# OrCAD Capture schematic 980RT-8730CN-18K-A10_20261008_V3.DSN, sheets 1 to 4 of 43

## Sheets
1 A0000_Config_C3680RF
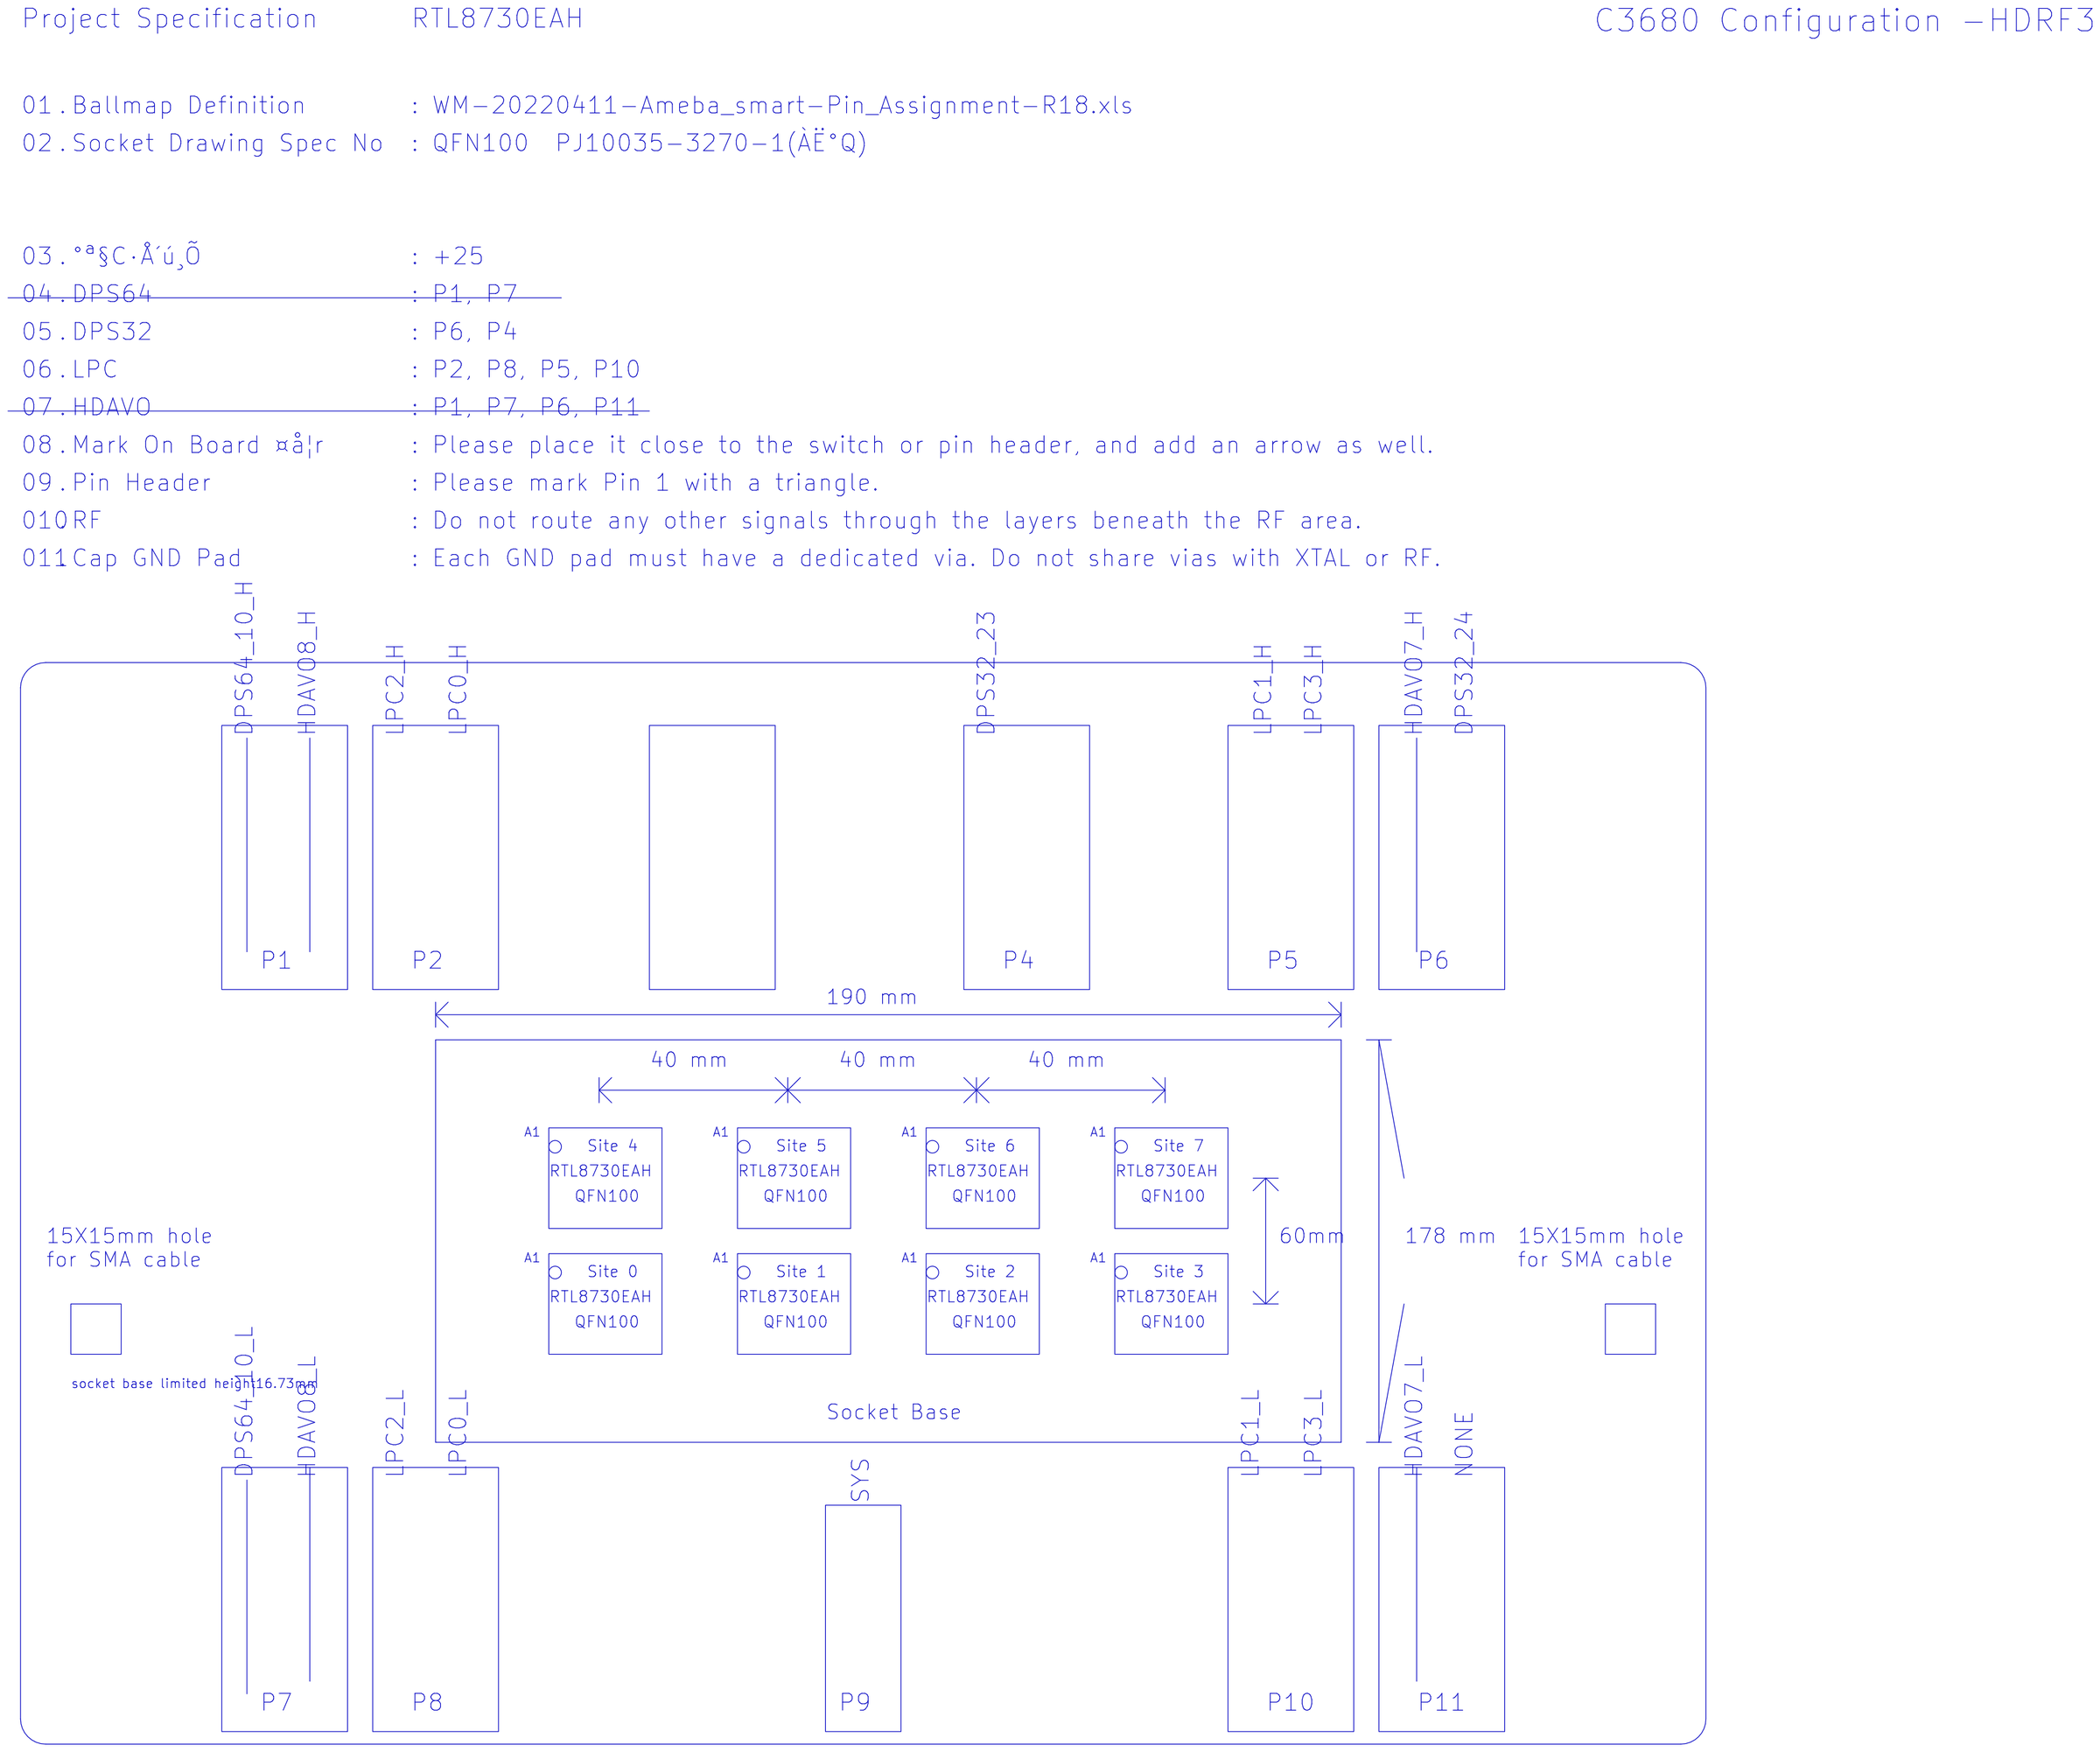
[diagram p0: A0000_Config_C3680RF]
2 P0001_S0_DUT1: size Custom
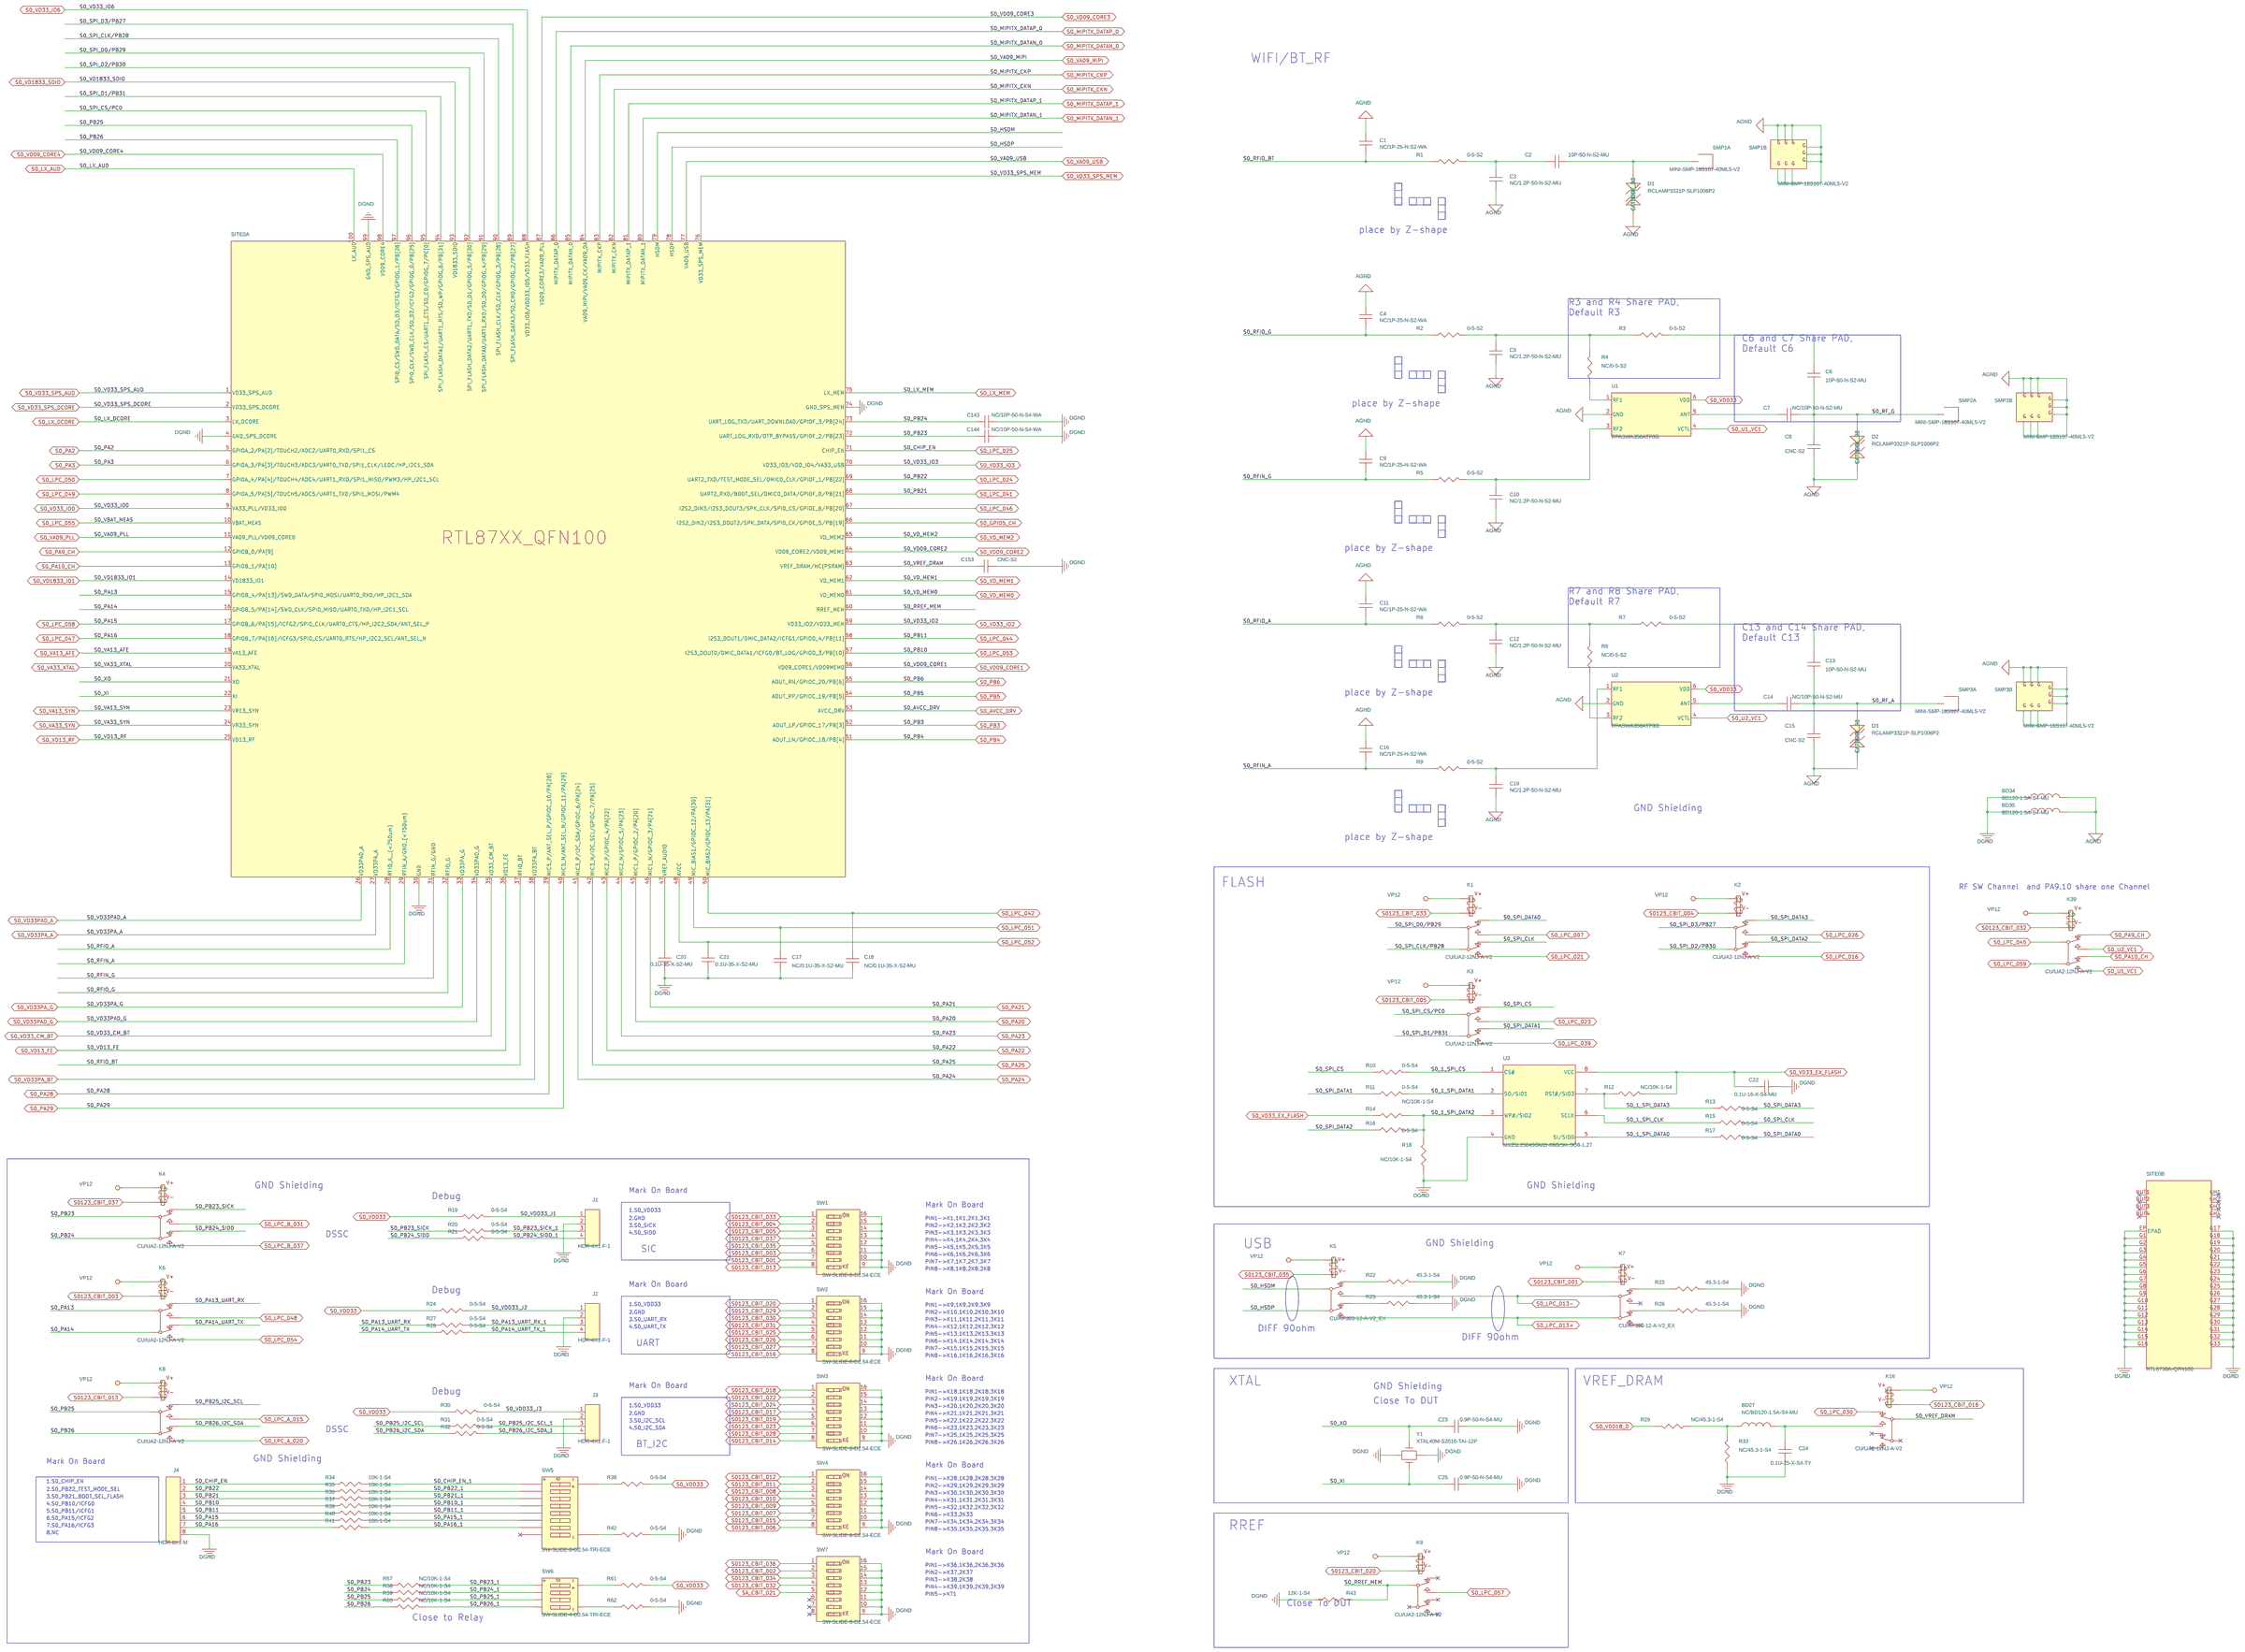
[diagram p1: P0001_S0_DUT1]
3 P0002_S0_Function-test: size A3
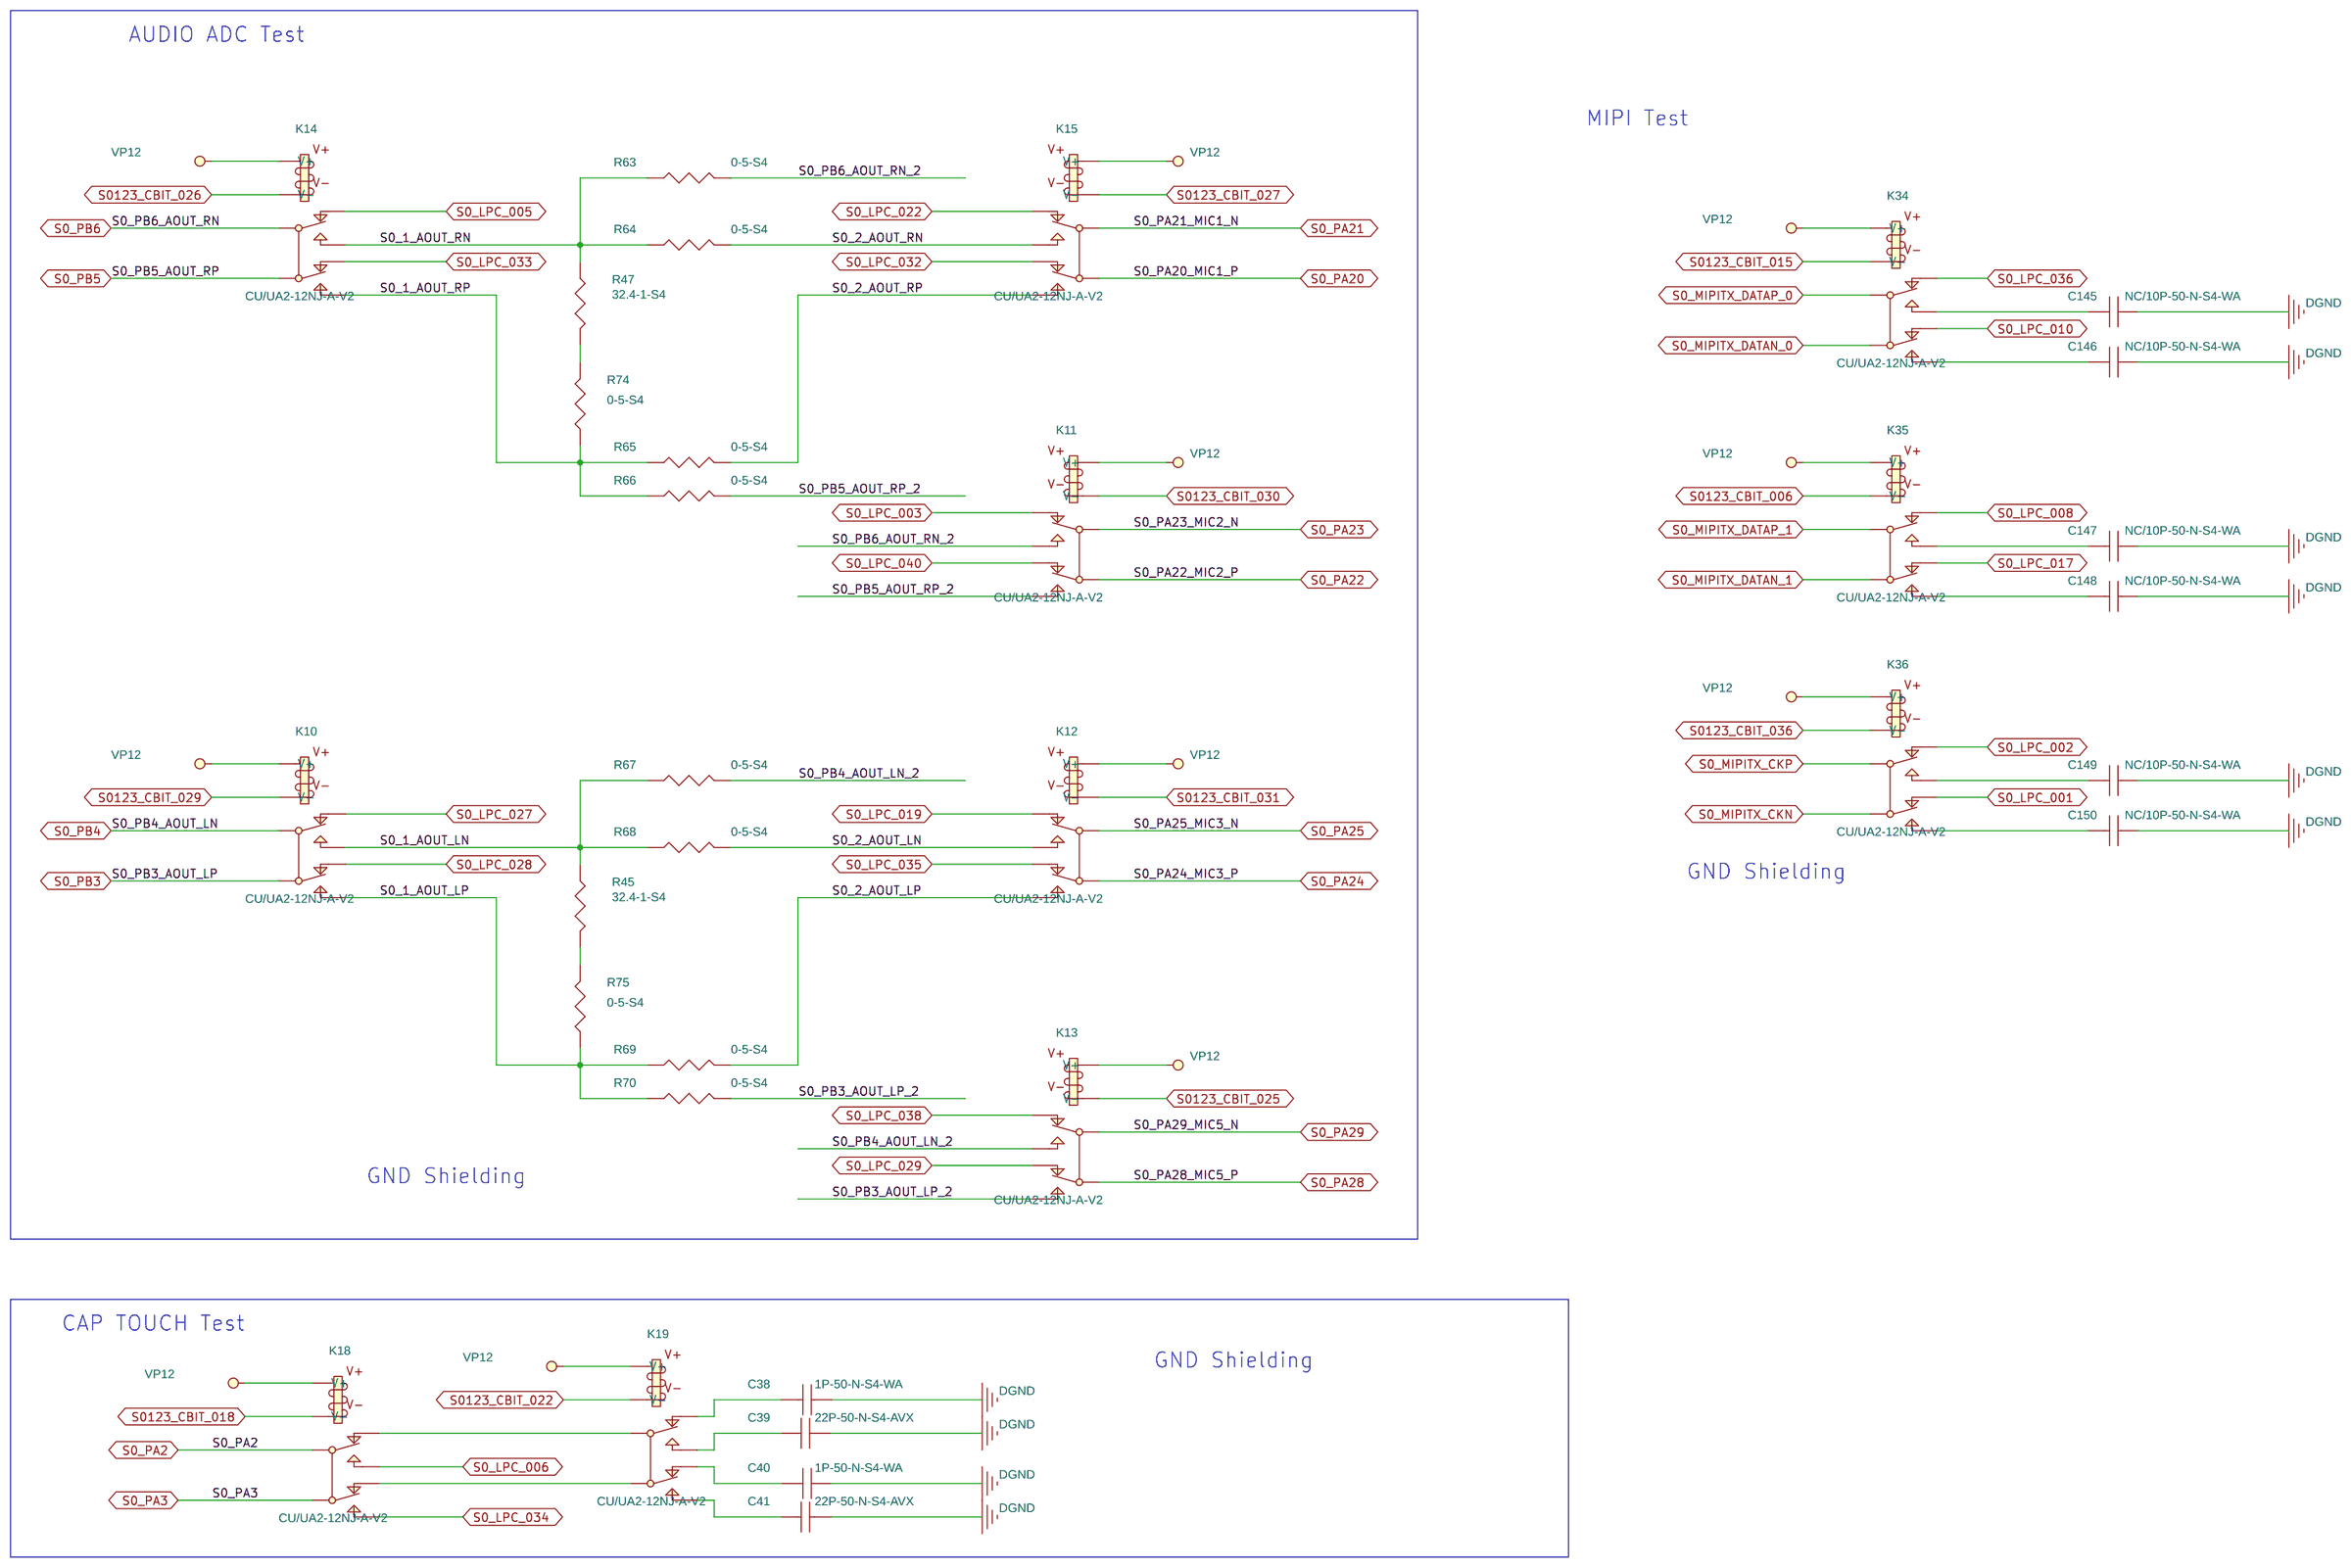
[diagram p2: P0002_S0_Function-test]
4 P0003_S0_Power: size A1
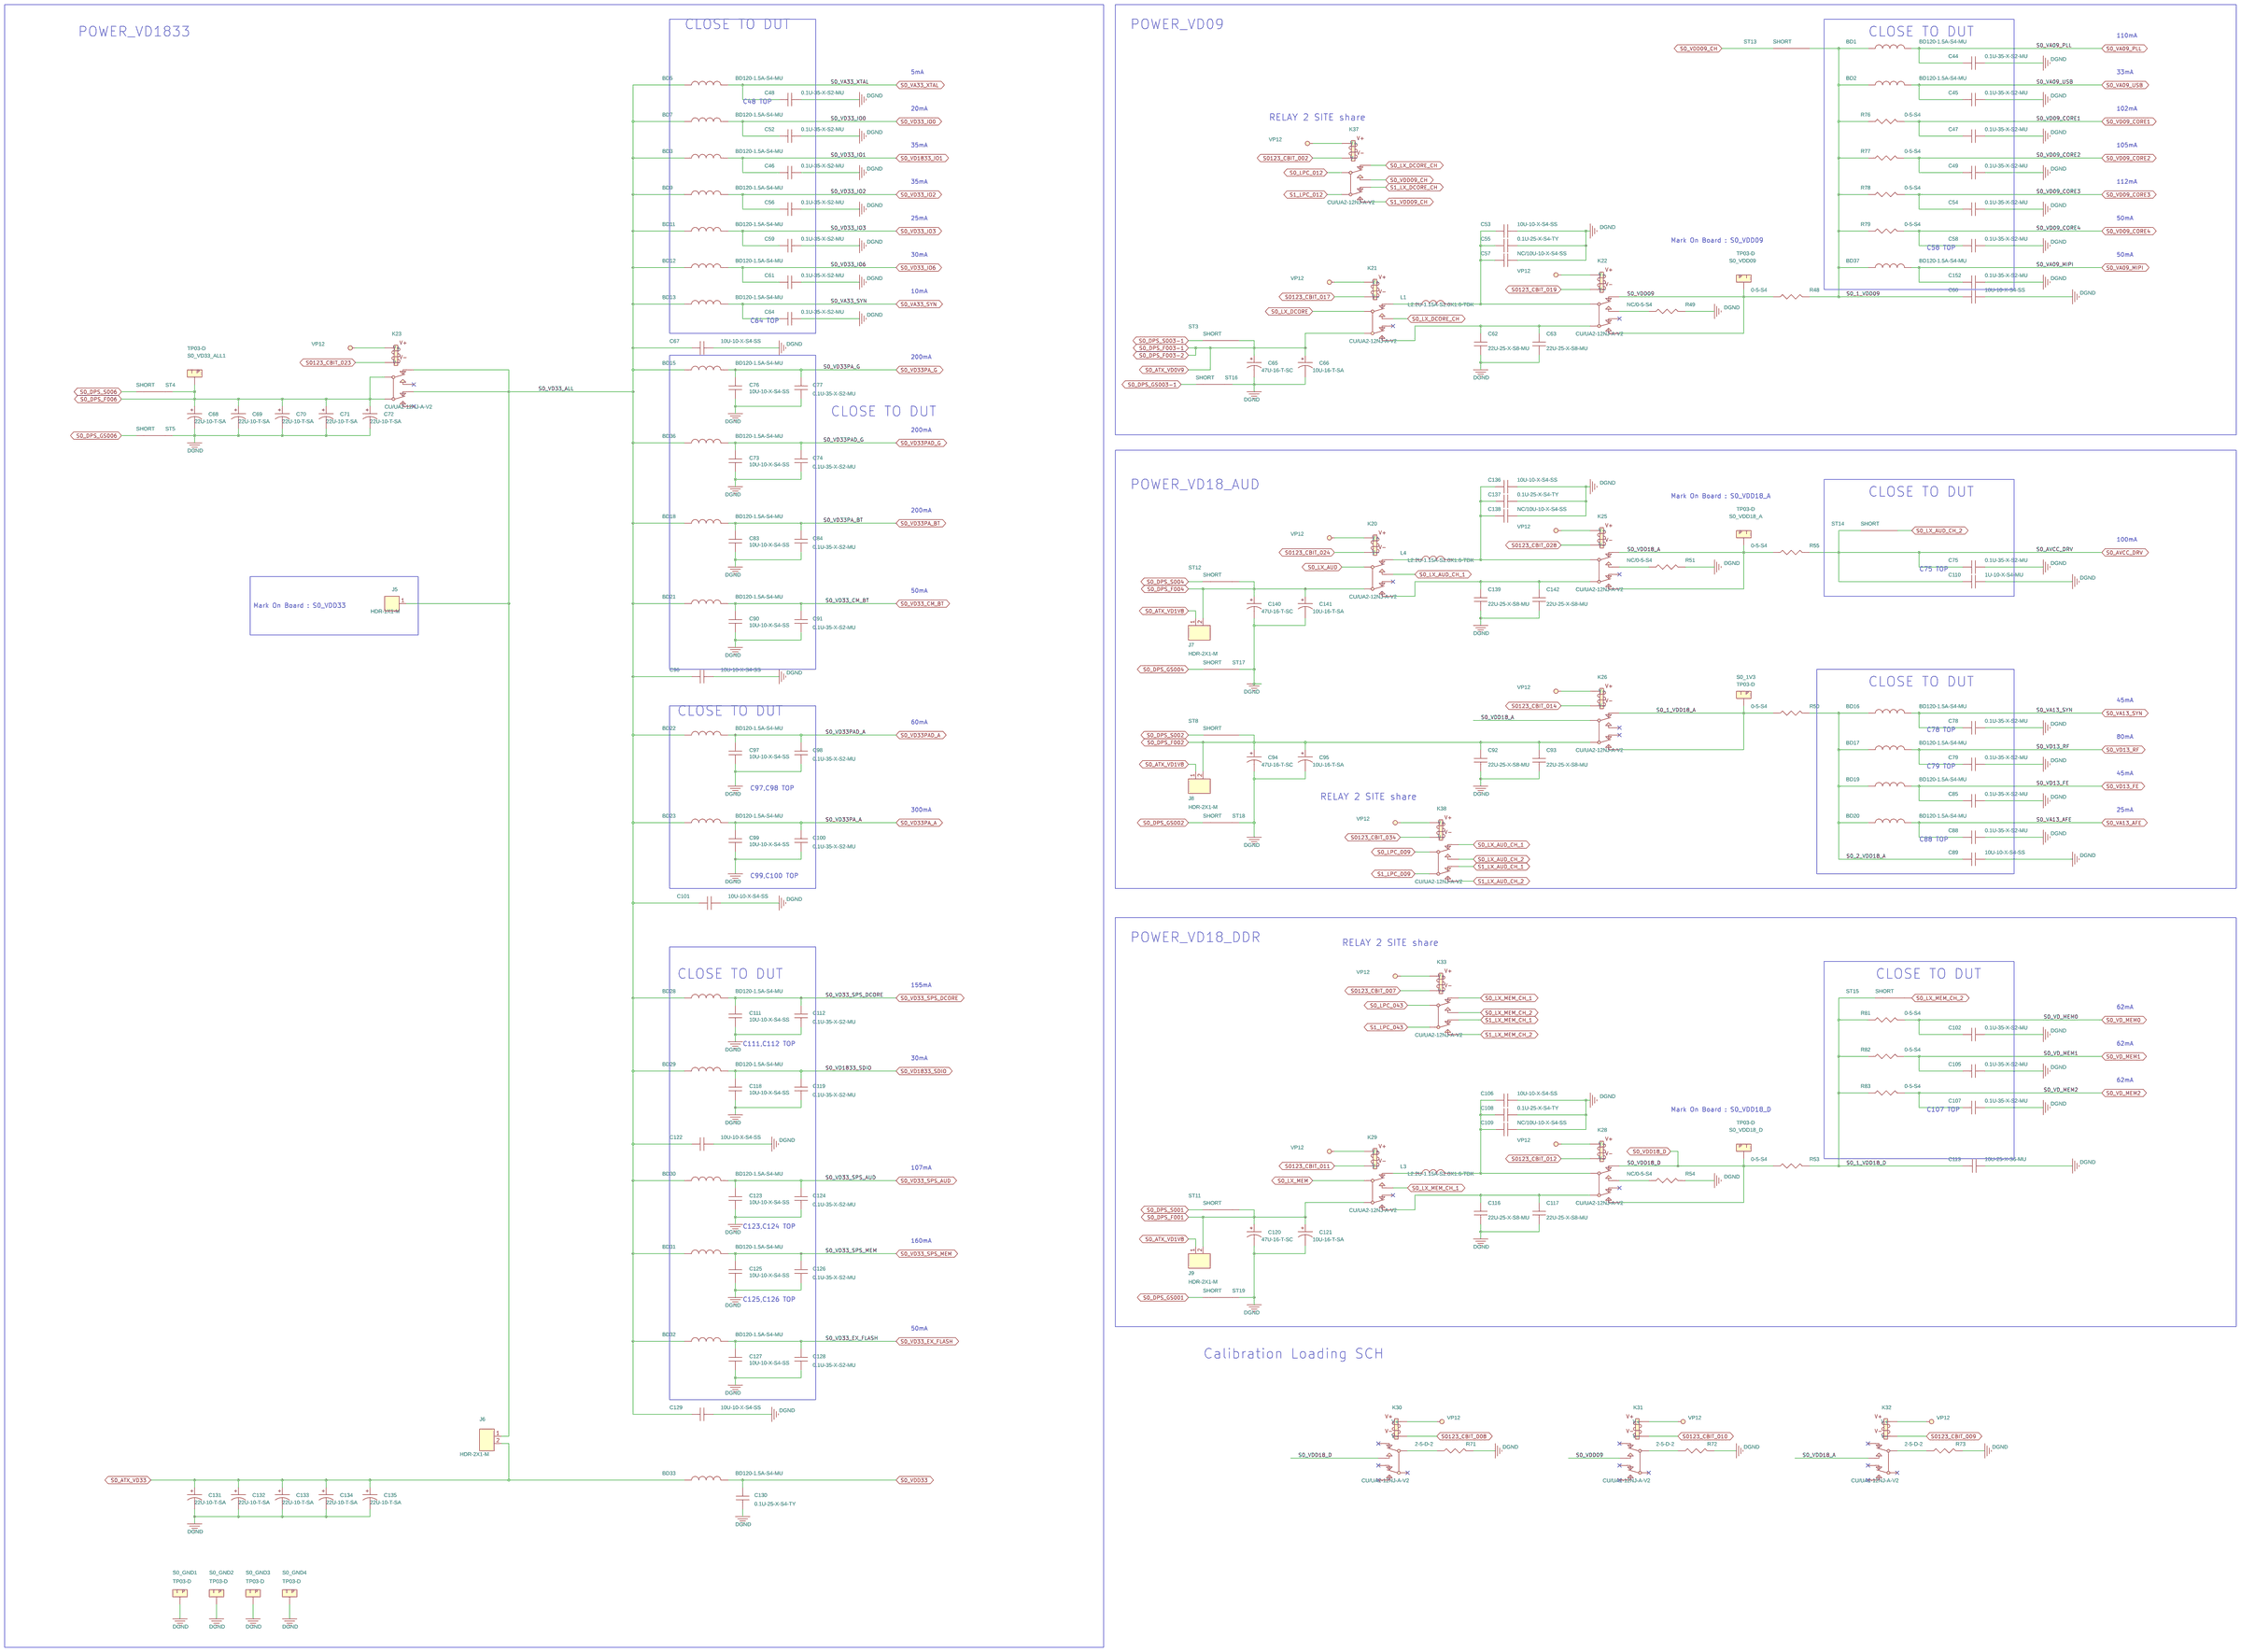
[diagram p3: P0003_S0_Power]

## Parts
sheet P0001_S0_DUT1
BD27  NC/BD120-1.5A-S4-MU  [FB0402]
BD34  BD120-1.5A-S4-MU  [FB0402]
BD35  BD120-1.5A-S4-MU  [FB0402]
C1  NC/1P-25-N-S2-WA  [C0201]
C2  10P-50-N-S2-MU  [C0201]
C3  NC/1.2P-50-N-S2-MU  [C0201]
C4  NC/1P-25-N-S2-WA  [C0201]
C5  NC/1.2P-50-N-S2-MU  [C0201]
C6  10P-50-N-S2-MU  [C0201]
C7  NC/10P-50-N-S2-MU  [C0201]
C8  CNC-S2  [C0201]
C9  NC/1P-25-N-S2-WA  [C0201]
C10  NC/1.2P-50-N-S2-MU  [C0201]
C11  NC/1P-25-N-S2-WA  [C0201]
C12  NC/1.2P-50-N-S2-MU  [C0201]
C13  10P-50-N-S2-MU  [C0201]
C14  NC/10P-50-N-S2-MU  [C0201]
C15  CNC-S2  [C0201]
C16  NC/1P-25-N-S2-WA  [C0201]
C17  NC/0.1U-35-X-S2-MU  [C0201]
C18  NC/0.1U-35-X-S2-MU  [C0201]
C19  NC/1.2P-50-N-S2-MU  [C0201]
C20  0.1U-35-X-S2-MU  [C0201]
C21  0.1U-35-X-S2-MU  [C0201]
C22  0.1U-16-X-S4-MU  [C0402]
C23  0.9P-50-N-S4-MU  [C0402]
C24  0.1U-25-X-S4-TY  [C0402]
C25  0.9P-50-N-S4-MU  [C0402]
C143  NC/10P-50-N-S4-WA  [C0402]
C144  NC/10P-50-N-S4-WA  [C0402]
C153  CNC-S2  [C0201]
D1  RCLAMP3321P-SLP1006P2  [DIODE_1X0P6MM]
D2  RCLAMP3321P-SLP1006P2  [DIODE_1X0P6MM]
D3  RCLAMP3321P-SLP1006P2  [DIODE_1X0P6MM]
J1  HDR-4X1-F-1  [CONN_4X1_2P54MM_FL10P5MM]
J2  HDR-4X1-F-1  [CONN_4X1_2P54MM_FL10P5MM]
J3  HDR-4X1-F-1  [CONN_4X1_2P54MM_FL10P5MM]
J4  HDR-8X1-M  [JP_8P_100]
K1  CU/UA2-12NJ-A-V2  [RL_NECUA2_12V_V2]
K2  CU/UA2-12NJ-A-V2  [RL_NECUA2_12V_V2]
K3  CU/UA2-12NJ-A-V2  [RL_NECUA2_12V_V2]
K4  CU/UA2-12NJ-A-V2  [RL_NECUA2_12V_V2]
K5  CU/RF303-12-A-V2_EX  [RL_RF303_12V_V2]
K6  CU/UA2-12NJ-A-V2  [RL_NECUA2_12V_V2]
K7  CU/RF303-12-A-V2_EX  [RL_RF303_12V_V2]
K8  CU/UA2-12NJ-A-V2  [RL_NECUA2_12V_V2]
K9  CU/UA2-12NJ-A-V2  [RL_NECUA2_12V_V2]
K16  CU/UA2-12NJ-A-V2  [RL_NECUA2_12V_V2]
K39  CU/UA2-12NJ-A-V2  [RL_NECUA2_12V_V2]
R1  0-5-S2  [R0201]
R2  0-5-S2  [R0201]
R3  0-5-S2  [R0201]
R4  NC/0-5-S2  [R0201]
R5  0-5-S2  [R0201]
R6  0-5-S2  [R0201]
R7  0-5-S2  [R0201]
R8  NC/0-5-S2  [R0201]
R9  0-5-S2  [R0201]
R10  0-5-S4  [R0402]
R11  0-5-S4  [R0402]
R12  NC/10K-1-S4  [R0402]
R13  0-5-S4  [R0402]
R14  NC/10K-1-S4  [R0402]
R15  0-5-S4  [R0402]
R16  0-5-S4  [R0402]
R17  0-5-S4  [R0402]
R18  NC/10K-1-S4  [R0402]
R19  0-5-S4  [R0402]
R20  0-5-S4  [R0402]
R21  0-5-S4  [R0402]
R22  45.3-1-S4  [R0402]
R23  45.3-1-S4  [R0402]
R24  0-5-S4  [R0402]
R25  45.3-1-S4  [R0402]
R26  45.3-1-S4  [R0402]
R27  0-5-S4  [R0402]
R28  0-5-S4  [R0402]
R29  NC/45.3-1-S4  [R0402]
R30  0-5-S4  [R0402]
R31  0-5-S4  [R0402]
R32  0-5-S4  [R0402]
R33  NC/45.3-1-S4  [R0402]
R34  10K-1-S4  [R0402]
R35  10K-1-S4  [R0402]
R36  10K-1-S4  [R0402]
R37  10K-1-S4  [R0402]
R38  0-5-S4  [R0402]
R39  10K-1-S4  [R0402]
R40  10K-1-S4  [R0402]
R41  10K-1-S4  [R0402]
R42  0-5-S4  [R0402]
R43  12K-1-S4  [R0402]
R57  NC/10K-1-S4  [R0402]
R58  NC/10K-1-S4  [R0402]
R59  NC/10K-1-S4  [R0402]
R60  NC/10K-1-S4  [R0402]
R61  0-5-S4  [R0402]
R62  0-5-S4  [R0402]
SITE0  RTL8730A-QFN100  [SK_QFN100P_0P35MM_MJC_L8730A]  (sections A,B)
SMP1  MINI-SMP-18S107-40ML5-V2  [CONN_SMP_18S107]  (sections A,B)
SMP2  MINI-SMP-18S107-40ML5-V2  [CONN_SMP_18S107]  (sections A,B)
SMP3  MINI-SMP-18S107-40ML5-V2  [CONN_SMP_18S107]  (sections A,B)
SW1  SW-SLIDE-8-D2.54-ECE  [SW_DIPX8_16P_H5MM]
SW2  SW-SLIDE-8-D2.54-ECE  [SW_DIPX8_16P_H5MM]
SW3  SW-SLIDE-8-D2.54-ECE  [SW_DIPX8_16P_H5MM]
SW4  SW-SLIDE-8-D2.54-ECE  [SW_DIPX8_16P_H5MM]
SW5  SW-SLIDE-8-D2.54-TRI-ECE  [SW_DIPX8P_2P54_MM_V2]
SW6  SW-SLIDE-4-D2.54-TRI-ECE  [SW_DIPX4P_2P54MM_ETD]
SW7  SW-SLIDE-8-D2.54-ECE  [SW_DIPX8_16P_H5MM]
U1  RFASWA358ATF0G  [RF_SW_GW2159_6P]
U2  RFASWA358ATF0G  [RF_SW_GW2159_6P]
U3  MX25L25645GM2I-08G/SK-SO8-1.27  [SK_SO8_1P27MM_LOTES]
Y1  XTAL40M-S2016-TAI-12P  [XTAL_2X1P6MM_4P_0P8MM]
sheet P0002_S0_Function-test
C38  1P-50-N-S4-WA  [C0402]
C39  22P-50-N-S4-AVX  [C0402]
C40  1P-50-N-S4-WA  [C0402]
C41  22P-50-N-S4-AVX  [C0402]
C145  NC/10P-50-N-S4-WA  [C0402]
C146  NC/10P-50-N-S4-WA  [C0402]
C147  NC/10P-50-N-S4-WA  [C0402]
C148  NC/10P-50-N-S4-WA  [C0402]
C149  NC/10P-50-N-S4-WA  [C0402]
C150  NC/10P-50-N-S4-WA  [C0402]
K10  CU/UA2-12NJ-A-V2  [RL_NECUA2_12V_V2]
K11  CU/UA2-12NJ-A-V2  [RL_NECUA2_12V_V2]
K12  CU/UA2-12NJ-A-V2  [RL_NECUA2_12V_V2]
K13  CU/UA2-12NJ-A-V2  [RL_NECUA2_12V_V2]
K14  CU/UA2-12NJ-A-V2  [RL_NECUA2_12V_V2]
K15  CU/UA2-12NJ-A-V2  [RL_NECUA2_12V_V2]
K18  CU/UA2-12NJ-A-V2  [RL_NECUA2_12V_V2]
K19  CU/UA2-12NJ-A-V2  [RL_NECUA2_12V_V2]
K34  CU/UA2-12NJ-A-V2  [RL_NECUA2_12V_V2]
K35  CU/UA2-12NJ-A-V2  [RL_NECUA2_12V_V2]
K36  CU/UA2-12NJ-A-V2  [RL_NECUA2_12V_V2]
R45  32.4-1-S4  [R0402]
R47  32.4-1-S4  [R0402]
R63  0-5-S4  [R0402]
R64  0-5-S4  [R0402]
R65  0-5-S4  [R0402]
R66  0-5-S4  [R0402]
R67  0-5-S4  [R0402]
R68  0-5-S4  [R0402]
R69  0-5-S4  [R0402]
R70  0-5-S4  [R0402]
R74  0-5-S4  [R0402]
R75  0-5-S4  [R0402]
sheet P0003_S0_Power
BD1  BD120-1.5A-S4-MU  [FB0402]
BD2  BD120-1.5A-S4-MU  [FB0402]
BD3  BD120-1.5A-S4-MU  [FB0402]
BD5  BD120-1.5A-S4-MU  [FB0402]
BD7  BD120-1.5A-S4-MU  [FB0402]
BD9  BD120-1.5A-S4-MU  [FB0402]
BD11  BD120-1.5A-S4-MU  [FB0402]
BD12  BD120-1.5A-S4-MU  [FB0402]
BD13  BD120-1.5A-S4-MU  [FB0402]
BD15  BD120-1.5A-S4-MU  [FB0402]
BD16  BD120-1.5A-S4-MU  [FB0402]
BD17  BD120-1.5A-S4-MU  [FB0402]
BD18  BD120-1.5A-S4-MU  [FB0402]
BD19  BD120-1.5A-S4-MU  [FB0402]
BD20  BD120-1.5A-S4-MU  [FB0402]
BD21  BD120-1.5A-S4-MU  [FB0402]
BD22  BD120-1.5A-S4-MU  [FB0402]
BD23  BD120-1.5A-S4-MU  [FB0402]
BD28  BD120-1.5A-S4-MU  [FB0402]
BD29  BD120-1.5A-S4-MU  [FB0402]
BD30  BD120-1.5A-S4-MU  [FB0402]
BD31  BD120-1.5A-S4-MU  [FB0402]
BD32  BD120-1.5A-S4-MU  [FB0402]
BD33  BD120-1.5A-S4-MU  [FB0402]
BD36  BD120-1.5A-S4-MU  [FB0402]
BD37  BD120-1.5A-S4-MU  [FB0402]
C44  0.1U-35-X-S2-MU  [C0201]
C45  0.1U-35-X-S2-MU  [C0201]
C46  0.1U-35-X-S2-MU  [C0201]
C47  0.1U-35-X-S2-MU  [C0201]
C48  0.1U-35-X-S2-MU  [C0201]
C49  0.1U-35-X-S2-MU  [C0201]
C52  0.1U-35-X-S2-MU  [C0201]
C53  10U-10-X-S4-SS  [C0402]
C54  0.1U-35-X-S2-MU  [C0201]
C55  0.1U-25-X-S4-TY  [C0402]
C56  0.1U-35-X-S2-MU  [C0201]
C57  NC/10U-10-X-S4-SS  [C0402]
C58  0.1U-35-X-S2-MU  [C0201]
C59  0.1U-35-X-S2-MU  [C0201]
C60  10U-10-X-S4-SS  [C0402]
C61  0.1U-35-X-S2-MU  [C0201]
C62  22U-25-X-S8-MU  [C0805]
C63  22U-25-X-S8-MU  [C0805]
C64  0.1U-35-X-S2-MU  [C0201]
C65  47U-16-T-SC  [CODE_C]
C66  10U-16-T-SA  [CODE_A]
C67  10U-10-X-S4-SS  [C0402]
C68  22U-10-T-SA  [CODE_A]
C69  22U-10-T-SA  [CODE_A]
C70  22U-10-T-SA  [CODE_A]
C71  22U-10-T-SA  [CODE_A]
C72  22U-10-T-SA  [CODE_A]
C73  10U-10-X-S4-SS  [C0402]
C74  0.1U-35-X-S2-MU  [C0201]
C75  0.1U-35-X-S2-MU  [C0201]
C76  10U-10-X-S4-SS  [C0402]
C77  0.1U-35-X-S2-MU  [C0201]
C78  0.1U-35-X-S2-MU  [C0201]
C79  0.1U-35-X-S2-MU  [C0201]
C83  10U-10-X-S4-SS  [C0402]
C84  0.1U-35-X-S2-MU  [C0201]
C85  0.1U-35-X-S2-MU  [C0201]
C88  0.1U-35-X-S2-MU  [C0201]
C89  10U-10-X-S4-SS  [C0402]
C90  10U-10-X-S4-SS  [C0402]
C91  0.1U-35-X-S2-MU  [C0201]
C92  22U-25-X-S8-MU  [C0805]
C93  22U-25-X-S8-MU  [C0805]
C94  47U-16-T-SC  [CODE_C]
C95  10U-16-T-SA  [CODE_A]
C96  10U-10-X-S4-SS  [C0402]
C97  10U-10-X-S4-SS  [C0402]
C98  0.1U-35-X-S2-MU  [C0201]
C99  10U-10-X-S4-SS  [C0402]
C100  0.1U-35-X-S2-MU  [C0201]
C101  10U-10-X-S4-SS  [C0402]
C102  0.1U-35-X-S2-MU  [C0201]
C105  0.1U-35-X-S2-MU  [C0201]
C106  10U-10-X-S4-SS  [C0402]
C107  0.1U-35-X-S2-MU  [C0201]
C108  0.1U-25-X-S4-TY  [C0402]
C109  NC/10U-10-X-S4-SS  [C0402]
C110  1U-10-X-S4-MU  [C0402]
C111  10U-10-X-S4-SS  [C0402]
C112  0.1U-35-X-S2-MU  [C0201]
C113  10U-25-X-S6-MU  [C0603]
C116  22U-25-X-S8-MU  [C0805]
C117  22U-25-X-S8-MU  [C0805]
C118  10U-10-X-S4-SS  [C0402]
C119  0.1U-35-X-S2-MU  [C0201]
C120  47U-16-T-SC  [CODE_C]
C121  10U-16-T-SA  [CODE_A]
C122  10U-10-X-S4-SS  [C0402]
C123  10U-10-X-S4-SS  [C0402]
C124  0.1U-35-X-S2-MU  [C0201]
C125  10U-10-X-S4-SS  [C0402]
C126  0.1U-35-X-S2-MU  [C0201]
C127  10U-10-X-S4-SS  [C0402]
C128  0.1U-35-X-S2-MU  [C0201]
C129  10U-10-X-S4-SS  [C0402]
C130  0.1U-25-X-S4-TY  [C0402]
C131  22U-10-T-SA  [CODE_A]
C132  22U-10-T-SA  [CODE_A]
C133  22U-10-T-SA  [CODE_A]
C134  22U-10-T-SA  [CODE_A]
C135  22U-10-T-SA  [CODE_A]
C136  10U-10-X-S4-SS  [C0402]
C137  0.1U-25-X-S4-TY  [C0402]
C138  NC/10U-10-X-S4-SS  [C0402]
C139  22U-25-X-S8-MU  [C0805]
C140  47U-16-T-SC  [CODE_C]
C141  10U-16-T-SA  [CODE_A]
C142  22U-25-X-S8-MU  [C0805]
C152  0.1U-35-X-S2-MU  [C0201]
J5  HDR-1X1-M  [JP_1P_RD070_040]
J6  HDR-2X1-M  [JP_2P_100]
J7  HDR-2X1-M  [JP_2P_100]
J8  HDR-2X1-M  [JP_2P_100]
J9  HDR-2X1-M  [JP_2P_100]
K20  CU/UA2-12NJ-A-V2  [RL_NECUA2_12V_V2]
K21  CU/UA2-12NJ-A-V2  [RL_NECUA2_12V_V2]
K22  CU/UA2-12NJ-A-V2  [RL_NECUA2_12V_V2]
K23  CU/UA2-12NJ-A-V2  [RL_NECUA2_12V_V2]
K25  CU/UA2-12NJ-A-V2  [RL_NECUA2_12V_V2]
K26  CU/UA2-12NJ-A-V2  [RL_NECUA2_12V_V2]
K28  CU/UA2-12NJ-A-V2  [RL_NECUA2_12V_V2]
K29  CU/UA2-12NJ-A-V2  [RL_NECUA2_12V_V2]
K30  CU/UA2-12NJ-A-V2  [RL_NECUA2_12V_V2]
K31  CU/UA2-12NJ-A-V2  [RL_NECUA2_12V_V2]
K32  CU/UA2-12NJ-A-V2  [RL_NECUA2_12V_V2]
K33  CU/UA2-12NJ-A-V2  [RL_NECUA2_12V_V2]
K37  CU/UA2-12NJ-A-V2  [RL_NECUA2_12V_V2]
K38  CU/UA2-12NJ-A-V2  [RL_NECUA2_12V_V2]
L1  L2.2U-1.15A-S2.0X1.6-TDK  [IND_VL252012E]
L3  L2.2U-1.15A-S2.0X1.6-TDK  [IND_VL252012E]
L4  L2.2U-1.15A-S2.0X1.6-TDK  [IND_VL252012E]
R48  0-5-S4  [R0402]
R49  NC/0-5-S4  [R0402]
R50  0-5-S4  [R0402]
R51  NC/0-5-S4  [R0402]
R53  0-5-S4  [R0402]
R54  NC/0-5-S4  [R0402]
R55  0-5-S4  [R0402]
R71  2-5-D-2  [RC02W_27MM]
R72  2-5-D-2  [RC02W_27MM]
R73  2-5-D-2  [RC02W_27MM]
R76  0-5-S4  [R0402]
R77  0-5-S4  [R0402]
R78  0-5-S4  [R0402]
R79  0-5-S4  [R0402]
R81  0-5-S4  [R0402]
R82  0-5-S4  [R0402]
R83  0-5-S4  [R0402]
S0_1V3  TP03-D  [TP_060_040]
S0_GND1  TP03-D  [TP_060_040]
S0_GND2  TP03-D  [TP_060_040]
S0_GND3  TP03-D  [TP_060_040]
S0_GND4  TP03-D  [TP_060_040]
S0_VD33_ALL1  TP03-D  [TP_060_040]
S0_VDD09  TP03-D  [TP_060_040]
S0_VDD18_A  TP03-D  [TP_060_040]
S0_VDD18_D  TP03-D  [TP_060_040]
ST3  SHORT  [DEFAULT_SHORT_SMALL]
ST4  SHORT  [DEFAULT_SHORT_SMALL]
ST5  SHORT  [DEFAULT_SHORT_SMALL]
ST8  SHORT  [DEFAULT_SHORT_SMALL]
ST11  SHORT  [DEFAULT_SHORT_SMALL]
ST12  SHORT  [DEFAULT_SHORT_SMALL]
ST13  SHORT  [DEFAULT_SHORT_SMALL]
ST14  SHORT  [DEFAULT_SHORT_SMALL]
ST15  SHORT  [DEFAULT_SHORT_SMALL]
ST16  SHORT  [DEFAULT_SHORT_SMALL]
ST17  SHORT  [DEFAULT_SHORT_SMALL]
ST18  SHORT  [DEFAULT_SHORT_SMALL]
ST19  SHORT  [DEFAULT_SHORT_SMALL]

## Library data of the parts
BD1-BD3 BD5 BD7 BD9 BD11-BD13 BD15-BD23 BD27-BD35 = BD120-1.5A-S4-MU
C1 C4 C9 C11 C16 = 1P-25-N-S2-WA
C2 C6 C7 C13 C14 = 10P-50-N-S2-MU
C3 C5 C10 C12 C19 = 1.2P-50-N-S2-MU
C8 C15 = CNC-S4
C17 C18 = 0.1U-35-X-S2-MU: KAIROSNAME: C46
C20 C21 = 0.1U-35-X-S2-MU: KAIROSNAME: C98
C22 = 0.1U-16-X-S4
C23 C25 C38 C40 = 10P-50-N-S4-MU-1
C24 C55 C108 C130 C137 = 0.1U-25-X-S4-TY
C143-C150 = 10P-50-N-S4-WA
C153 = 0.1U-35-X-S2-MU: KAIROSNAME: C48
D1-D3 = RCLAMP3321P-SLP1006P2
J1-J3 = HDR-4X1-F-1
J4 = HDR-8X1-M
K1-K4 K6 K8-K15 K18-K23 K25 K26 K28 K29 = CU_UA2-12NJ-A-V2
K5 K7 = CU_RF303-12-A-V2_EX
K16 = CU_UA2-12NJ-A-V2: KAIROSNAME: K2
K39 = CU_UA2-12NJ-A-V2: KAIROSNAME: K1
R1-R9 = 0-5-S2
R10 R11 R13 R15-R17 R19-R21 R24 R27 R28 R30-R32 R38 R42 R48-R51 R53-R55 R61-R70 R76-R79 R81-R83 = 0-5-S4
R12 R14 R18 R34-R37 R39-R41 R57-R60 = 10K-1-S4
R22 R23 R25 R26 R29 R33 = 45.3-1-S4
R43 = 12K-1-S4
SITE0 = RTL8730A-QFN100
SMP1 = MINI-SMP-18S107-40ML5-V2: KAIROSNAME: SMP1A
SMP2 = MINI-SMP-18S107-40ML5-V2: KAIROSNAME: SMP2A
SMP3 = MINI-SMP-18S107-40ML5-V2: KAIROSNAME: SMP3A
SW1-SW4 SW7 = SW-SLIDE-8-D2.54-ECE
SW5 = SW-SLIDE-8-D2.54-TRI-ECE
SW6 = SW-SLIDE-4-D2.54-TRI-ECE
U1 U2 = RFASWA358ATF0G
U3 = MX25R6435FM2IL0-SOP8
Y1 = XTAL40M-S2016-TAI-12P
C39 C41 = 33P-50-N-S4-WA
K34-K36 = CU_UA2-12NJ-A-V2: KAIROSNAME: K15
R45 R47 = 32.4-1-S4
R74 R75 = 0-5-S4: KAIROSNAME: R65
BD36 = BD120-1.5A-S4-MU: KAIROSNAME: BD15
BD37 = BD120-1.5A-S4-MU: KAIROSNAME: BD10
C44-C49 C52 C54 C56 C58 C59 C61 C64 C75 C77-C79 C84 C85 C88 C91 C98 C100 C102 C105 C107 C112 C119 C124 C126 C128 = 0.1U-35-X-S2-MU
C53 C57 C60 C67 C76 C83 C89 C90 C96 C97 C99 C101 C106 C109-C111 C118 C122 C123 C125 C127 C129 C136 C138 = 10U-10-X-S4-SS
C62 C63 C92 C93 C116 C117 C139 C142 = 22U-25-X-S8-MU
C65 C94 C120 C140 = 47U-16-T-SC
C66 C95 C121 C141 = 10U-16-T-SA
C68-C72 C131-C135 = 22U-10-T-SA
C73 = 10U-10-X-S4-SS: KAIROSNAME: C76
C74 = 0.1U-35-X-S2-MU: KAIROSNAME: C77
C113 = 10U-25-X-S6-MU
C152 = 0.1U-35-X-S2-MU: KAIROSNAME: C58
J5 = HDR-1X1-M
J6-J9 = HDR-2X1-M
K30-K32 = CU_UA2-12NJ-A-V2: KAIROSNAME: K28
K33 = CU_UA2-12NJ-A-V2: KAIROSNAME: K26
K37 K38 = CU_UA2-12NJ-A-V2: KAIROSNAME: K22
L1 L3 L4 = L2.2U-1.15A-S2.0X1.6-TDK
R71-R73 = 2-5-D-2
S0_1V3 = TP03-D: KAIROSNAME: S0_TP_VD3
S0_GND1-S0_GND4 S0_VD33_ALL1 S0_VDD09 S0_VDD18_A S0_VDD18_D = TP03-D
ST3-ST5 ST8 ST11 ST12 = SHORT
ST13-ST15 = SHORT: KAIROSNAME: ST3
ST16-ST19 = SHORT: KAIROSNAME: ST5

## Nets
AGND: BD34.2 BD35.2 C1.1 C3.2 C4.1 C5.2 C8.2 C9.1 C10.2 C11.1 C12.2 C15.2 C16.1 C19.2 D1.2(CATHODE_D2) D2.2(CATHODE_D2) D3.2(CATHODE_D2) SMP1.G1 SMP1.G2 SMP1.G3 SMP1.G4 SMP1.G5 SMP1.G6 SMP1.G7 SMP1.G8 SMP1.G9 SMP2.G1 SMP2.G2 SMP2.G3 SMP2.G4 SMP2.G5 SMP2.G6 SMP2.G7 SMP2.G8 SMP2.G9 SMP3.G1 SMP3.G2 SMP3.G3 SMP3.G4 SMP3.G5 SMP3.G6 SMP3.G7 SMP3.G8 SMP3.G9 U1.2(GND) U2.2(GND) ; also on sheet 5 8 11 14 17 20 23
DGND: BD34.1 BD35.1 C17.1 C18.1 C20.2 C21.2 C22.2 C23.1 C24.2 C25.1 C38.1 C39.2 C40.1 C41.2 C44.2 C45.2 C46.2 C47.2 C48.2 C49.2 C52.2 C53.2 C54.2 C55.2 C56.2 C57.2 C58.2 C59.2 C60.2 C61.2 C62.2 C63.2 C64.2 C65.2 C66.2 C67.2 C68.2 C69.2 C70.2 C71.2 C72.2 C73.2 C74.2 C75.2 C76.2 C77.2 C78.2 C79.2 C83.2 C84.2 C85.2 C88.2 C89.2 C90.2 C91.2 C92.2 C93.2 C94.2 C95.2 C96.2 C97.2 C98.2 C99.2 C100.2 C101.2 C102.2 C105.2 C106.2 C107.2 C108.2 C109.2 C110.2 C111.2 C112.2 C113.1 C116.2 C117.2 C118.2 C119.2 C120.2 C121.2 C122.2 C123.2 C124.2 C125.2 C126.2 C127.2 C128.2 C129.2 C130.2 C131.2 C132.2 C133.2 C134.2 C135.2 C136.2 C137.2 C138.2 C139.2 C140.2 C141.2 C142.2 C143.1 C144.1 C145.1 C146.1 C147.1 C148.1 C149.1 C150.1 C152.2 C153.2 J1.2 J2.2 J3.2 J4.8 R18.1 R22.2 R23.2 R25.2 R26.2 R33.1 R42.2 R43.2 R49.2 R51.2 R54.2 R62.2 R71.2 R72.2 R73.2 S0_GND1.1(TP) S0_GND2.1(TP) S0_GND3.1(TP) S0_GND4.1(TP) SITE0.4(GND_SPS_DCORE) SITE0.30(GND) SITE0.74(GND_SPS_MEM) SITE0.99(GND_SPS_AUD) SITE0.EP(EPAD) SITE0.G1 SITE0.G2 SITE0.G3 SITE0.G4 SITE0.G5 SITE0.G6 SITE0.G7 SITE0.G8 SITE0.G9 SITE0.G10 SITE0.G11 SITE0.G12 SITE0.G13 SITE0.G14 SITE0.G15 SITE0.G16 SITE0.G17 SITE0.G18 SITE0.G19 SITE0.G20 SITE0.G21 SITE0.G22 SITE0.G23 SITE0.G24 SITE0.G25 SITE0.G26 SITE0.G27 SITE0.G28 SITE0.G29 SITE0.G30 SITE0.G31 SITE0.G32 SITE0.G33 ST5.2 ST16.2 ST17.2 ST18.2 ST19.2 SW1.9 SW1.10 SW1.11 SW1.12 SW1.13 SW1.14 SW1.15 SW1.16 SW2.9 SW2.10 SW2.11 SW2.12 SW2.13 SW2.14 SW2.15 SW2.16 SW3.9 SW3.10 SW3.11 SW3.12 SW3.13 SW3.14 SW3.15 SW3.16 SW4.9 SW4.10 SW4.11 SW4.12 SW4.13 SW4.14 SW4.15 SW4.16 SW7.9 SW7.10 SW7.11 SW7.12 SW7.13 SW7.14 SW7.15 SW7.16 U3.4(GND) Y1.2 Y1.4 ; also on sheet 5 6 7 8 9 10 11 12 13 14 15 16 17 18 19 20 21 22 23 24 25 26 27 29 30 32 34 37 39
S0_1_AOUT_LN: K10.4 R45.1 R67.1 R68.1
S0_1_AOUT_LP: K10.5 R69.1 R70.1 R75.1
S0_1_AOUT_RN: K14.4 R47.1 R63.1 R64.1
S0_1_AOUT_RP: K14.5 R65.1 R66.1 R74.1
S0_1_SPI_CLK: R15.1 U3.6(SCLK)
S0_1_SPI_CS: R10.2 U3.1(CS#)
S0_1_SPI_DATA0: R17.1 U3.5(SI/SIO0)
S0_1_SPI_DATA1: R11.2 U3.2(SO/SIO1)
S0_1_SPI_DATA2: R14.2 R16.2 R18.2 U3.3(WP#/SIO2)
S0_1_SPI_DATA3: R12.1 R13.1 U3.7(RST#/SIO3)
S0_1_VDD09: BD1.1 BD2.1 BD37.1 C60.1 R48.2 R76.1 R77.1 R78.1 R79.1 ST13.2
S0_1_VDD18_A: K26.2 K26.5 R50.1 S0_1V3.1(TP)
S0_1_VDD18_D: C113.2 R53.2 R81.1 R82.1 R83.1 ST15.1
S0_2_AOUT_LN: K12.4 R68.2
S0_2_AOUT_LP: K12.5 R69.2
S0_2_AOUT_RN: K15.4 R64.2
S0_2_AOUT_RP: K15.5 R65.2
S0_2_VDD18_A: BD16.1 BD17.1 BD19.1 BD20.1 C89.1 R50.2
S0_ATX_VD0V9: C65.1 C66.1 K21.6 ST3.2 ; also on sheet 27
S0_ATX_VD1V8: J7.1 J8.1 J9.1 ; also on sheet 27
S0_ATX_VD33: BD33.1 C131.1 C132.1 C133.1 C134.1 C135.1 J6.2 ; also on sheet 27
S0_AVCC_DRV: C75.1 C110.1 R55.2 SITE0.53(AVCC_DRV) ST14.1
S0_CHIP_EN_1: R34.2 SW5.1
S0_DPS_F001: C120.1 C121.1 J9.2 K29.6 ST11.2
S0_DPS_F002: C92.1 C93.1 C94.1 C95.1 J8.2 K26.6 ST8.2
S0_DPS_F004: C140.1 C141.1 J7.2 K20.6 ST12.2
S0_DPS_F006: C68.1 C69.1 C70.1 C71.1 C72.1 K23.3 K23.6 S0_VD33_ALL1.1(TP) ST4.2
S0_DPS_GS001: ST19.1
S0_DPS_GS002: ST18.1
S0_DPS_GS003-1: ST16.1
S0_DPS_GS004: ST17.1
S0_DPS_GS006: ST5.1
S0_DPS_S001: ST11.1
S0_DPS_S002: ST8.1
S0_DPS_S003-1: ST3.1
S0_DPS_S004: ST12.1
S0_DPS_S006: ST4.1
S0_GPIO5_CH: SITE0.66(I2S2_DIN2/I2S3_DOUT2/SPK_DATA/SPI0_CK/GPIOE_5/PB[19]) ; also on sheet 26
S0_HSDM: K5.8 SITE0.79(HSDM)
S0_HSDP: K5.2 SITE0.78(HSDP)
S0_LPC_001: K36.7
S0_LPC_002: K36.2
S0_LPC_003: K11.2
S0_LPC_005: K14.2
S0_LPC_006: K18.4
S0_LPC_007: K1.4
S0_LPC_008: K35.2
S0_LPC_009: K38.3
S0_LPC_010: K34.7
S0_LPC_012: K37.3
S0_LPC_013+: K5.3 K7.2
S0_LPC_013-: K5.7 K7.8
S0_LPC_016: K2.5
S0_LPC_017: K35.7
S0_LPC_019: K12.2
S0_LPC_021: K1.5
S0_LPC_022: K15.2
S0_LPC_023: K3.4
S0_LPC_024: J4.2 R35.1 SITE0.69(UART2_TXD/TEST_MODE_SEL/DMIC0_CLK/GPIOF_1/PB[22])
S0_LPC_025: J4.1 R34.1 SITE0.71(CHIP_EN)
S0_LPC_026: K2.4
S0_LPC_027: K10.2
S0_LPC_028: K10.7
S0_LPC_029: K13.7
S0_LPC_030: K16.2
S0_LPC_032: K15.7
S0_LPC_033: K14.7
S0_LPC_034: K18.5
S0_LPC_035: K12.7
S0_LPC_036: K34.2
S0_LPC_038: K13.2
S0_LPC_039: K3.5
S0_LPC_040: K11.7
S0_LPC_041: J4.3 R36.1 SITE0.68(UART2_RXD/BOOT_SEL/DMIC0_DATA/GPIOF_0/PB[21])
S0_LPC_042: C18.2 SITE0.50(MIC_BIAS2/GPIOC_13/PA[31])
S0_LPC_043: K33.3
S0_LPC_044: J4.5 R39.1 SITE0.58(I2S3_DOUT1/DMIC_DATA2/ICFG1/GPIOD_4/PB[11])
S0_LPC_045: K39.3
S0_LPC_046: SITE0.67(I2S2_DIN3/I2S3_DOUT3/SPK_CLK/SPI0_CS/GPIOE_6/PB[20])
S0_LPC_047: J4.7 R41.1 SITE0.18(GPIOB_7/PA[16]/ICFG3/SPI0_CS/UART0_RTS/HP_I2C2_SCL/ANT_SEL_N)
S0_LPC_048: K6.4
S0_LPC_049: SITE0.8(GPIOA_5/PA[5]/TOUCH5/ADC5/UART1_TXD/SPI1_MOSI/PWM4)
S0_LPC_050: SITE0.7(GPIOA_4/PA[4]/TOUCH4/ADC4/UART1_RXD/SPI1_MISO/PWM3/HP_I2C1_SCL)
S0_LPC_051: C17.2 SITE0.49(MIC_BIAS1/GPIOC_12/PA[30])
S0_LPC_052: C21.1 SITE0.48(AVCC)
S0_LPC_053: J4.4 R37.1 SITE0.57(I2S3_DOUT0/DMIC_DATA1/ICFG0/BT_LOG/GPIOD_3/PB[10])
S0_LPC_054: K6.5
S0_LPC_055: SITE0.10(VBAT_MEAS)
S0_LPC_057: K9.4
S0_LPC_058: J4.6 R40.1 SITE0.17(GPIOB_6/PA[15]/ICFG2/SPI0_CLK/UART0_CTS/HP_I2C2_SDA/ANT_SEL_P)
S0_LPC_059: K39.6
S0_LPC_A_015: K8.4
S0_LPC_A_020: K8.5
S0_LPC_B_031: K4.4
S0_LPC_B_037: K4.5
S0_LX_AUD: K20.3 SITE0.100(LX_AUD)
S0_LX_AUD_CH_1: K20.4 K38.2
S0_LX_AUD_CH_2: K38.4 ST14.2
S0_LX_DCORE: K21.3 SITE0.3(LX_DCORE)
S0_LX_DCORE_CH: K21.4 K37.2
S0_LX_MEM: K29.3 SITE0.75(LX_MEM)
S0_LX_MEM_CH_1: K29.4 K33.2
S0_LX_MEM_CH_2: K33.4 ST15.2
S0_MIPITX_CKN: K36.6 SITE0.82(MIPITX_CKN)
S0_MIPITX_CKP: K36.3 SITE0.83(MIPITX_CKP)
S0_MIPITX_DATAN_0: K34.6 SITE0.85(MIPITX_DATAN_0)
S0_MIPITX_DATAN_1: K35.6 SITE0.80(MIPITX_DATAN_1)
S0_MIPITX_DATAP_0: K34.3 SITE0.86(MIPITX_DATAP_0)
S0_MIPITX_DATAP_1: K35.3 SITE0.81(MIPITX_DATAP_1)
S0_PA2: K18.3 SITE0.5(GPIOA_2/PA[2]/TOUCH2/ADC2/UART0_RXD/SPI1_CS)
S0_PA3: K18.6 SITE0.6(GPIOA_3/PA[3]/TOUCH3/ADC3/UART0_TXD/SPI1_CLK/LEDC/HP_I2C1_SDA)
S0_PA9_CH: K39.2 SITE0.12(GPIOB_0/PA[9])
S0_PA10_CH: K39.7 SITE0.13(GPIOB_1/PA[10])
S0_PA13: K6.3 SITE0.15(GPIOB_4/PA[13]/SWD_DATA/SPI0_MOSI/UART0_RXD/HP_I2C1_SDA)
S0_PA13_UART_RX: K6.2 R27.1
S0_PA13_UART_RX_1: J2.3 R27.2
S0_PA14: K6.6 SITE0.16(GPIOB_5/PA[14]/SWD_CLK/SPI0_MISO/UART0_TXD/HP_I2C1_SCL)
S0_PA14_UART_TX: K6.7 R28.1
S0_PA14_UART_TX_1: J2.4 R28.2
S0_PA15_1: R40.2 SW5.6
S0_PA16_1: R41.2 SW5.7
S0_PA20: K15.6 SITE0.45(MIC1_P/GPIOC_2/PA[20])
S0_PA21: K15.3 SITE0.46(MIC1_N/GPIOC_3/PA[21])
S0_PA22: K11.6 SITE0.43(MIC2_P/GPIOC_4/PA[22])
S0_PA23: K11.3 SITE0.44(MIC2_N/GPIOC_5/PA[23])
S0_PA24: K12.6 SITE0.41(MIC3_P/I2C_SDA/GPIOC_6/PA[24])
S0_PA25: K12.3 SITE0.42(MIC3_N/I2C_SCL/GPIOC_7/PA[25])
S0_PA28: K13.6 SITE0.39(MIC5_P/ANT_SEL_P/GPIOC_10/PA[28])
S0_PA29: K13.3 SITE0.40(MIC5_N/ANT_SEL_N/GPIOC_11/PA[29])
S0_PB3: K10.6 SITE0.52(AOUT_LP/GPIOC_17/PB[3])
S0_PB3_AOUT_LP_2: K13.5 R70.2
S0_PB4: K10.3 SITE0.51(AOUT_LN/GPIOC_18/PB[4])
S0_PB4_AOUT_LN_2: K13.4 R67.2
S0_PB5: K14.6 SITE0.54(AOUT_RP/GPIOC_19/PB[5])
S0_PB5_AOUT_RP_2: K11.5 R66.2
S0_PB6: K14.3 SITE0.55(AOUT_RN/GPIOC_20/PB[6])
S0_PB6_AOUT_RN_2: K11.4 R63.2
S0_PB10_1: R37.2 SW5.4
S0_PB11_1: R39.2 SW5.5
S0_PB21_1: R36.2 SW5.3
S0_PB22_1: R35.2 SW5.2
S0_PB23: C144.2 K4.3 R57.1 SITE0.72(UART_LOG_RXD/OTP_BYPASS/GPIOF_2/PB[23])
S0_PB23_1: R57.2 SW6.1
S0_PB23_SICK: K4.2 R20.1
S0_PB23_SICK_1: J1.3 R20.2
S0_PB24: C143.2 K4.6 R58.1 SITE0.73(UART_LOG_TXD/UART_DOWNLOAD/GPIOF_3/PB[24])
S0_PB24_1: R58.2 SW6.2
S0_PB24_SIDD: K4.7 R21.1
S0_PB24_SIDD_1: J1.4 R21.2
S0_PB25: K8.3 R59.1 SITE0.96(SPI0_CLK/SWD_CLK/SD_D2/ICFG2/GPIOG_0/PB[25])
S0_PB25_1: R59.2 SW6.3
S0_PB25_I2C_SCL: K8.2 R31.1
S0_PB25_I2C_SCL_1: J3.3 R31.2
S0_PB26: K8.6 R60.1 SITE0.97(SPI0_CS/SWD_DATA/SD_D3/ICFG3/GPIOG_1/PB[26])
S0_PB26_1: R60.2 SW6.4
S0_PB26_I2C_SDA: K8.7 R32.1
S0_PB26_I2C_SDA_1: J3.4 R32.2
S0_RF_A: C13.1 C14.1 C15.1 D3.1(CATHODE_D1) SMP3.1
S0_RF_G: C6.1 C7.1 C8.1 D2.1(CATHODE_D1) SMP2.1
S0_RFIN_A: C16.2 R9.1 SITE0.29(RFIN_A/GND_(<750um))
S0_RFIN_G: C9.2 R5.1 SITE0.31(RFIN_G/GND)
S0_RFIO_A: C11.2 R6.1 SITE0.28(RFIO_A__(<750um))
S0_RFIO_BT: C1.2 R1.1 SITE0.37(RFIO_BT)
S0_RFIO_G: C4.2 R2.1 SITE0.32(RFIO_G)
S0_RREF_MEM: K9.3 R43.1 SITE0.60(RREF_MEM)
S0_SPI_CLK: K1.7 R15.2
S0_SPI_CLK/PB28: K1.6 SITE0.90(SPI_FLASH_CLK/SD_CLK/GPIOG_3/PB[28])
S0_SPI_CS: K3.2 R10.1
S0_SPI_CS/PC0: K3.3 SITE0.95(SPI_FLASH_CS/UART1_CTS/SD_CD/GPIOG_7/PC[0])
S0_SPI_D0/PB29: K1.3 SITE0.91(SPI_FLASH_DATA0/UART1_RXD/SD_D0/GPIOG_4/PB[29])
S0_SPI_D1/PB31: K3.6 SITE0.94(SPI_FLASH_DATA1/UART1_RTS/SD_WP/GPIOG_6/PB[31])
S0_SPI_D2/PB30: K2.6 SITE0.92(SPI_FLASH_DATA2/UART1_TXD/SD_D1/GPIOG_5/PB[30])
S0_SPI_D3/PB27: K2.3 SITE0.89(SPI_FLASH_DATA3/SD_CMD/GPIOG_2/PB[27])
S0_SPI_DATA0: K1.2 R17.2
S0_SPI_DATA1: K3.7 R11.1
S0_SPI_DATA2: K2.7 R16.1
S0_SPI_DATA3: K2.2 R13.2
S0_U1_VC1: K39.5 U1.4(VCTL)
S0_U2_VC1: K39.4 U2.4(VCTL)
S0_VA09_MIPI: BD37.2 C152.1 SITE0.84(VA09_MIPI/VA09_CK/VA09_DA)
S0_VA09_PLL: BD1.2 C44.1 SITE0.11(VA09_PLL/VD09_CORE0)
S0_VA09_USB: BD2.2 C45.1 SITE0.77(VA09_USB)
S0_VA13_AFE: BD20.2 C88.1 SITE0.19(VA13_AFE)
S0_VA13_SYN: BD16.2 C78.1 SITE0.23(VR13_SYN)
S0_VA33_SYN: BD13.2 C64.1 SITE0.24(VR33_SYN)
S0_VA33_XTAL: BD5.2 C48.1 SITE0.20(VA33_XTAL)
S0_VD09_CORE1: C47.1 R76.2 SITE0.56(VD09_CORE1/VD09MEM0)
S0_VD09_CORE2: C49.1 R77.2 SITE0.64(VD09_CORE2/VD09_MEM1)
S0_VD09_CORE3: C54.1 R78.2 SITE0.87(VD09_CORE3/VA09_PLL)
S0_VD09_CORE4: C58.1 R79.2 SITE0.98(VD09_CORE4)
S0_VD13_FE: BD19.2 C85.1 SITE0.36(VD13_FE)
S0_VD13_RF: BD17.2 C79.1 SITE0.25(VD13_RF)
S0_VD33_ALL: BD3.1 BD5.1 BD7.1 BD9.1 BD11.1 BD12.1 BD13.1 BD15.1 BD18.1 BD21.1 BD22.1 BD23.1 BD28.1 BD29.1 BD30.1 BD31.1 BD32.1 BD36.1 C67.1 C96.1 C101.1 C122.1 C129.1 J5.1 J6.1 K23.2 K23.7
S0_VD33_CM_BT: BD21.2 C90.1 C91.1 SITE0.35(VD33_CM_BT)
S0_VD33_EX_FLASH: BD32.2 C22.1 C127.1 C128.1 R12.2 R14.1 U3.8(VCC)
S0_VD33_IO0: BD7.2 C52.1 SITE0.9(VA33_PLL/VD33_IO0)
S0_VD33_IO2: BD9.2 C56.1 SITE0.59(VD33_IO2/VD33_MEM)
S0_VD33_IO3: BD11.2 C59.1 SITE0.70(VD33_IO3/VDD_IO4/VA33_USB)
S0_VD33_IO6: BD12.2 C61.1 SITE0.88(VD33_IO6/VDD33_IO5/VD33_FLASH)
S0_VD33_SPS_AUD: BD30.2 C123.1 C124.1 SITE0.1(VD33_SPS_AUD)
S0_VD33_SPS_DCORE: BD28.2 C111.1 C112.1 SITE0.2(VD33_SPS_DCORE)
S0_VD33_SPS_MEM: BD31.2 C125.1 C126.1 SITE0.76(VD33_SPS_MEM)
S0_VD33PA_A: BD23.2 C99.1 C100.1 SITE0.27(VD33PA_A)
S0_VD33PA_BT: BD18.2 C83.1 C84.1 SITE0.38(VD33PA_BT)
S0_VD33PA_G: BD15.2 C76.1 C77.1 SITE0.33(VD33PA_G)
S0_VD33PAD_A: BD22.2 C97.1 C98.1 SITE0.26(VD33PAD_A)
S0_VD33PAD_G: BD36.2 C73.1 C74.1 SITE0.34(VD33PAD_G)
S0_VD1833_IO1: BD3.2 C46.1 SITE0.14(VD1833_IO1)
S0_VD1833_SDIO: BD29.2 C118.1 C119.1 SITE0.93(VD1833_SDIO)
S0_VD_MEM0: C102.1 R81.2 SITE0.61(VD_MEM0)
S0_VD_MEM1: C105.1 R82.2 SITE0.62(VD_MEM1)
S0_VD_MEM2: C107.1 R83.2 SITE0.65(VD_MEM2)
S0_VDD09: K22.2 K22.5 K31.4 R48.1 S0_VDD09.1(TP)
S0_VDD09_CH: K37.4 ST13.1
S0_VDD18_A: K25.2 K25.5 K26.3 K32.4 R55.1 S0_VDD18_A.1(TP)
S0_VDD18_D: K28.2 K28.5 K30.4 R29.2 R53.1 S0_VDD18_D.1(TP)
S0_VDD33: BD33.2 C130.1 R19.1 R24.1 R30.1 R38.2 R61.2 U1.6(VDD) U2.6(VDD)
S0_VDD33_J1: J1.1 R19.2
S0_VDD33_J2: J2.1 R24.2
S0_VDD33_J3: J3.1 R30.2
S0_VREF_DRAM: C153.1 K16.3 SITE0.63(VREF_DRAM/NC(PSRAM))
S0_XI: C25.2 SITE0.22(XI) Y1.1
S0_XO: C23.2 SITE0.21(XO) Y1.3
S1_LPC_009: K38.6
S1_LPC_012: K37.6
S1_LPC_043: K33.6
S1_LX_AUD_CH_1: K38.7 ; also on sheet 7
S1_LX_AUD_CH_2: K38.5 ; also on sheet 7
S1_LX_DCORE_CH: K37.7 ; also on sheet 7
S1_LX_MEM_CH_1: K33.7 ; also on sheet 7
S1_LX_MEM_CH_2: K33.5 ; also on sheet 7
S1_VDD09_CH: K37.5 ; also on sheet 7
S0123_CBIT_001: K7.9(V-) SW1.7 ; also on sheet 5 8 11
S0123_CBIT_002: K37.8(V-) SW7.2 ; also on sheet 10
S0123_CBIT_003: K6.8(V-) SW1.6 ; also on sheet 5 8 11
S0123_CBIT_004: K2.8(V-) SW1.2 ; also on sheet 5 8 11
S0123_CBIT_005: K3.8(V-) SW1.3 ; also on sheet 5 8 11
S0123_CBIT_006: K35.8(V-) SW4.8 ; also on sheet 6 9 12
S0123_CBIT_007: K33.8(V-) SW4.6 ; also on sheet 10
S0123_CBIT_008: K30.8(V-) SW4.3 ; also on sheet 7 10 13
S0123_CBIT_009: K32.8(V-) SW4.5 ; also on sheet 7 10 13
S0123_CBIT_010: K31.8(V-) SW4.4 ; also on sheet 7 10 13
S0123_CBIT_011: K29.8(V-) SW4.2 ; also on sheet 7 10 13
S0123_CBIT_012: K28.8(V-) SW4.1 ; also on sheet 7 10 13
S0123_CBIT_013: K8.8(V-) SW1.8 ; also on sheet 5 8 11
S0123_CBIT_014: K26.8(V-) SW3.8 ; also on sheet 7 10 13
S0123_CBIT_015: K34.8(V-) SW4.7 ; also on sheet 6 9 12
S0123_CBIT_016: K16.8(V-) SW2.8 ; also on sheet 5 8 11
S0123_CBIT_017: K21.8(V-) SW3.4 ; also on sheet 7 10 13
S0123_CBIT_018: K18.8(V-) SW3.1 ; also on sheet 6 9 12
S0123_CBIT_019: K22.8(V-) SW3.5 ; also on sheet 7 10 13
S0123_CBIT_020: K9.8(V-) SW2.1 ; also on sheet 5 8 11
S0123_CBIT_022: K19.8(V-) SW3.2 ; also on sheet 6 9 12
S0123_CBIT_023: K23.8(V-) SW3.6 ; also on sheet 7 10 13
S0123_CBIT_024: K20.8(V-) SW3.3 ; also on sheet 7 10 13
S0123_CBIT_025: K13.8(V-) SW2.5 ; also on sheet 6 9 12
S0123_CBIT_026: K14.8(V-) SW2.6 ; also on sheet 6 9 12
S0123_CBIT_027: K15.8(V-) SW2.7 ; also on sheet 6 9 12
S0123_CBIT_028: K25.8(V-) SW3.7 ; also on sheet 7 10 13
S0123_CBIT_029: K10.8(V-) SW2.2 ; also on sheet 6 9 12
S0123_CBIT_030: K11.8(V-) SW2.3 ; also on sheet 6 9 12
S0123_CBIT_031: K12.8(V-) SW2.4 ; also on sheet 6 9 12
S0123_CBIT_032: K39.8(V-) SW7.4 ; also on sheet 5 8 11
S0123_CBIT_033: K1.8(V-) SW1.1 ; also on sheet 5 8 11
S0123_CBIT_034: K38.8(V-) SW7.3 ; also on sheet 10
S0123_CBIT_035: K5.9(V-) SW1.5 ; also on sheet 5 8 11
S0123_CBIT_036: K36.8(V-) SW7.1 ; also on sheet 6 9 12
S0123_CBIT_037: K4.8(V-) SW1.4 ; also on sheet 5 8 11
SA_CBIT_021: SW7.5 ; also on sheet 26
VP12: K1.1(V+) K2.1(V+) K3.1(V+) K4.1(V+) K5.1(V+) K6.1(V+) K7.1(V+) K8.1(V+) K9.1(V+) K10.1(V+) K11.1(V+) K12.1(V+) K13.1(V+) K14.1(V+) K15.1(V+) K16.1(V+) K18.1(V+) K19.1(V+) K20.1(V+) K21.1(V+) K22.1(V+) K23.1(V+) K25.1(V+) K26.1(V+) K28.1(V+) K29.1(V+) K30.1(V+) K31.1(V+) K32.1(V+) K33.1(V+) K34.1(V+) K35.1(V+) K36.1(V+) K37.1(V+) K38.1(V+) K39.1(V+) ; also on sheet 5 6 7 8 9 10 11 12 13 14 15 16 17 18 19 20 21 22 23 24 25 26 27 29 38
N24979212: R38.1 SW5.10
N24979216: R42.1 SW5.9
N24989047: C10.1 R5.2 U1.3(RF2)
N24989128: C7.2 U1.5(ANT)
N24989237: R4.1 U1.1(RF1)
N24989519: C6.2 R3.2
N24989550: C19.1 R9.2 U2.1(RF1)
N24989582: C14.2 U2.5(ANT)
N24989672: C12.1 R6.2 R7.1 R8.2
N24989686: C13.2 R7.2
N24989857: BD27.2 C24.1 K16.4
N24989916: K5.6 R22.1
N24989920: K5.4 R25.1
N24989997: R8.1 U2.3(RF2)
N24990019: C5.1 R2.2 R3.1 R4.2
N24990271: C2.1 C3.1 R1.2
N24990291: C2.2 D1.1(CATHODE_D1) SMP1.1
N25003725: K7.6 R23.1
N25003728: K7.4 R26.1
N25009100: K18.2 K19.3
N25009102: K18.7 K19.6
N25009119: C39.1 K19.4
N25009121: C38.2 K19.2
N25009152: C41.1 K19.5
N25009154: C40.2 K19.7
N25018635: K21.2 L1.1
N25019559: K29.2 L3.1
N25019667: C106.1 C108.1 C109.1 K28.3 L3.2
N25019718: K28.4 R54.1
N25019726: C116.1 C117.1 K28.6 K29.5
N25019871: C53.1 C55.1 C57.1 K22.3 L1.2
N25019924: K22.4 R49.1
N25019943: C62.1 C63.1 K21.5 K22.6
N25095240: K20.2 L4.1
N25095242: C136.1 C137.1 C138.1 K25.3 L4.2
N25095269: K25.4 R51.1
N25095276: C139.1 C142.1 K20.5 K25.6
N25103211: BD27.1 R29.1 R33.2
N25107005: R61.1 SW6.6
N25107009: R62.1 SW6.5
N25114262: R47.2 R74.2
N25614045: K30.3 R71.1
N25614052: K31.3 R72.1
N25614059: K32.3 R73.1
N25867897: R45.2 R75.2
N25938555: C20.1 SITE0.47(VREF_AUDIO)
N25967988: C145.2 K34.4
N25967991: C146.2 K34.5
N25968094: C147.2 K35.4
N25968096: C148.2 K35.5
N25968164: C149.2 K36.4
N25968166: C150.2 K36.5

Not connected (* = marked no-connect by the designer): K7 3* 7*; K9 2* 5* 6* 7*; K16 5* 6* 7*; K20 7*; K21 7*; K22 7*; K23 4* 5*; K25 7*; K26 4* 7*; K28 7*; K29 7*; K30 2* 5* 6* 7*; K31 2* 5* 6* 7*; K32 2* 5* 6* 7*; SITE0 GH1* GH2* GH3* GH4* NUT1* NUT2* NUT3* NUT4*; SW5 8*; SW7 6* 7* 8*

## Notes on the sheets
sheet 1
- Project Specification
- RTL8730EAH
- C3680 Configuration -HDRF3
- 01
- .
- Ballmap Definition
- : WM-20220411-Ameba_smart-Pin_Assignment-R18.xls
- 02
- .
- Socket Drawing Spec No
- : QFN100  PJ10035-3270-1(ÀË°Q)
- 03
- .
- °ª§C·Å´ú¸Õ
- : +25
- 04
- .
- DPS64
- : P1, P7
- 05
- .
- DPS32
- : P6, P4
- 06
- .
- LPC
- : P2, P8, P5, P10
- 07
- .
- HDAVO
- : P1, P7, P6, P11
- 08
- .
- Mark On Board ¤å¦r
- : Please place it close to the switch or pin header, and add an arrow as well.
- 09
- .
- Pin Header
- : Please mark Pin 1 with a triangle.
- 010
- .
- RF
- : Do not route any other signals through the layers beneath the RF area.
- 011
- .
- Cap GND Pad
- : Each GND pad must have a dedicated via. Do not share vias with XTAL or RF.
- DPS64_10_H
- HDAVO8_H
- LPC2_H
- LPC0_H
- DPS32_23
- LPC1_H
- LPC3_H
- HDAVO7_H
- DPS32_24
- P1
- P2
- P4
- P5
- P6
- 190 mm
- 40 mm
- 40 mm
- 40 mm
- A1
- A1
- A1
- A1
- Site 4
- Site 5
- Site 6
- Site 7
- RTL8730EAH
- RTL8730EAH
- RTL8730EAH
- RTL8730EAH
- QFN100
- QFN100
- QFN100
- QFN100
- 15X15mm hole
  for SMA cable
- 60mm
- 178 mm
- 15X15mm hole
  for SMA cable
- A1
- A1
- A1
- A1
- Site 0
- Site 1
- Site 2
- Site 3
- RTL8730EAH
- RTL8730EAH
- RTL8730EAH
- RTL8730EAH
- QFN100
- QFN100
- QFN100
- QFN100
- socket base limited height16.73mm
- Socket Base
- DPS64_10_L
- HDAVO8_L
- LPC2_L
- LPC0_L
- LPC1_L
- LPC3_L
- HDAVO7_L
- NONE
- SYS
- P7
- P8
- P9
- P10
- P11
sheet 2
- WIFI/BT_RF
- place by Z-shape
- R3 and R4 Share PAD,
  Default R3
- C6 and C7 Share PAD,
  Default C6
- place by Z-shape
- place by Z-shape
- R7 and R8 Share PAD,
  Default R7
- C13 and C14 Share PAD,
  Default C13
- place by Z-shape
- GND Shielding
- place by Z-shape
- FLASH
- RF SW Channel  and PA9.10 share one Channel
- GND Shielding
- GND Shielding
- Debug
- Mark On Board
- Mark On Board
- 1.S0_VDD33
- 2.GND
- PIN1->K1,1K1,2K1,3K1
- 3.S0_SICK
- PIN2->K2,1K2,2K2,3K2
- DSSC
- 4.S0_SIDD
- PIN3->K3,1K3,2K3,3K3
- PIN4->K4,1K4,2K4,3K4
- USB
- GND Shielding
- SIC
- PIN5->K5,1K5,2K5,3K5
- PIN6->K6,1K6,2K6,3K6
- PIN7->K7,1K7,2K7,3K7
- PIN8->K8,1K8,2K8,3K8
- Debug
- Mark On Board
- Mark On Board
- 1.S0_VDD33
- PIN1->K9,1K9,2K9,3K9
- 2.GND
- PIN2->K10,1K10,2K10,3K10
- 3.S0_UART_RX
- PIN3->K11,1K11,2K11,3K11
- 4.S0_UART_TX
- PIN4->K12,1K12,2K12,3K12
- DIFF 90ohm
- PIN5->K13,1K13,2K13,3K13
- DIFF 90ohm
- UART
- PIN6->K14,1K14,2K14,3K14
- PIN7->K15,1K15,2K15,3K15
- PIN8->K16,1K16,2K16,3K16
- Mark On Board
- XTAL
- VREF_DRAM
- Debug
- Mark On Board
- PIN1->K18,1K18,2K18,3K18
- GND Shielding
- PIN2->K19,1K19,2K19,3K19
- Close To DUT
- 1.S0_VDD33
- PIN3->K20,1K20,2K20,3K20
- 2.GND
- PIN4->K21,1K21,2K21,3K21
- 3.S0_I2C_SCL
- PIN5->K22,1K22,2K22,3K22
- DSSC
- 4.S0_I2C_SDA
- PIN6->K23,1K23,2K23,3K23
- BT_I2C
- PIN7->K25,1K25,2K25,3K25
- PIN8->K26,1K26,2K26,3K26
- GND Shielding
- Mark On Board
- Mark On Board
- 1.S0_CHIP_EN
- PIN1->K28,1K28,2K28,3K28
- PIN2->K29,1K29,2K29,3K29
- 2.S0_PB22_TEST_MODE_SEL
- PIN3->K30,1K30,2K30,3K30
- 3.S0_PB21_BOOT_SEL_FLASH
- PIN4->K31,1K31,2K31,3K31
- 4.S0_PB10/ICFG0
- 5.S0_PB11/ICFG1
- PIN5->K32,1K32,2K32,3K32
- 6.S0_PA15/ICFG2
- PIN6->K33,2K33
- 7.S0_PA16/ICFG3
- PIN7->K34,1K34,2K34,3K34
- RREF
- 8.NC
- PIN8->K35,1K35,2K35,3K35
- Mark On Board
- PIN1->K36,1K36,2K36,3K36
- PIN2->K37,2K37
- PIN3->K38,2K38
- PIN4->K39,1K39,2K39,3K39
- PIN5->KT1
- Close To DUT
- Close to Relay
sheet 3
- AUDIO ADC Test
- MIPI Test
- GND Shielding
- GND Shielding
- CAP TOUCH Test
- GND Shielding
sheet 4
- CLOSE TO DUT
- POWER_VD09
- POWER_VD1833
- CLOSE TO DUT
- 110mA
- 5mA
- 33mA
- C48 TOP
- 20mA
- 102mA
- RELAY 2 SITE share
- 35mA
- 105mA
- 35mA
- 112mA
- 25mA
- 50mA
- Mark On Board : S0_VDD09
- C58 TOP
- 30mA
- 50mA
- 10mA
- C64 TOP
- 200mA
- CLOSE TO DUT
- 200mA
- POWER_VD18_AUD
- CLOSE TO DUT
- Mark On Board : S0_VDD18_A
- 200mA
- 100mA
- C75 TOP
- 50mA
- Mark On Board : S0_VDD33
- CLOSE TO DUT
- CLOSE TO DUT
- 45mA
- 60mA
- C78 TOP
- 80mA
- C79 TOP
- 45mA
- C97,C98 TOP
- RELAY 2 SITE share
- 300mA
- 25mA
- C88 TOP
- C99,C100 TOP
- POWER_VD18_DDR
- RELAY 2 SITE share
- CLOSE TO DUT
- CLOSE TO DUT
- 155mA
- 62mA
- C111,C112 TOP
- 62mA
- 30mA
- 62mA
- Mark On Board : S0_VDD18_D
- C107 TOP
- 107mA
- C123,C124 TOP
- 160mA
- C125,C126 TOP
- 50mA
- Calibration Loading SCH
